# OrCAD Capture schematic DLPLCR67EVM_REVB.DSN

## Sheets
1 PAGE-07 Important Notice
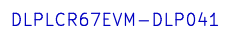
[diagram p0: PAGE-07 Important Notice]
2 PAGE-01 Title Page
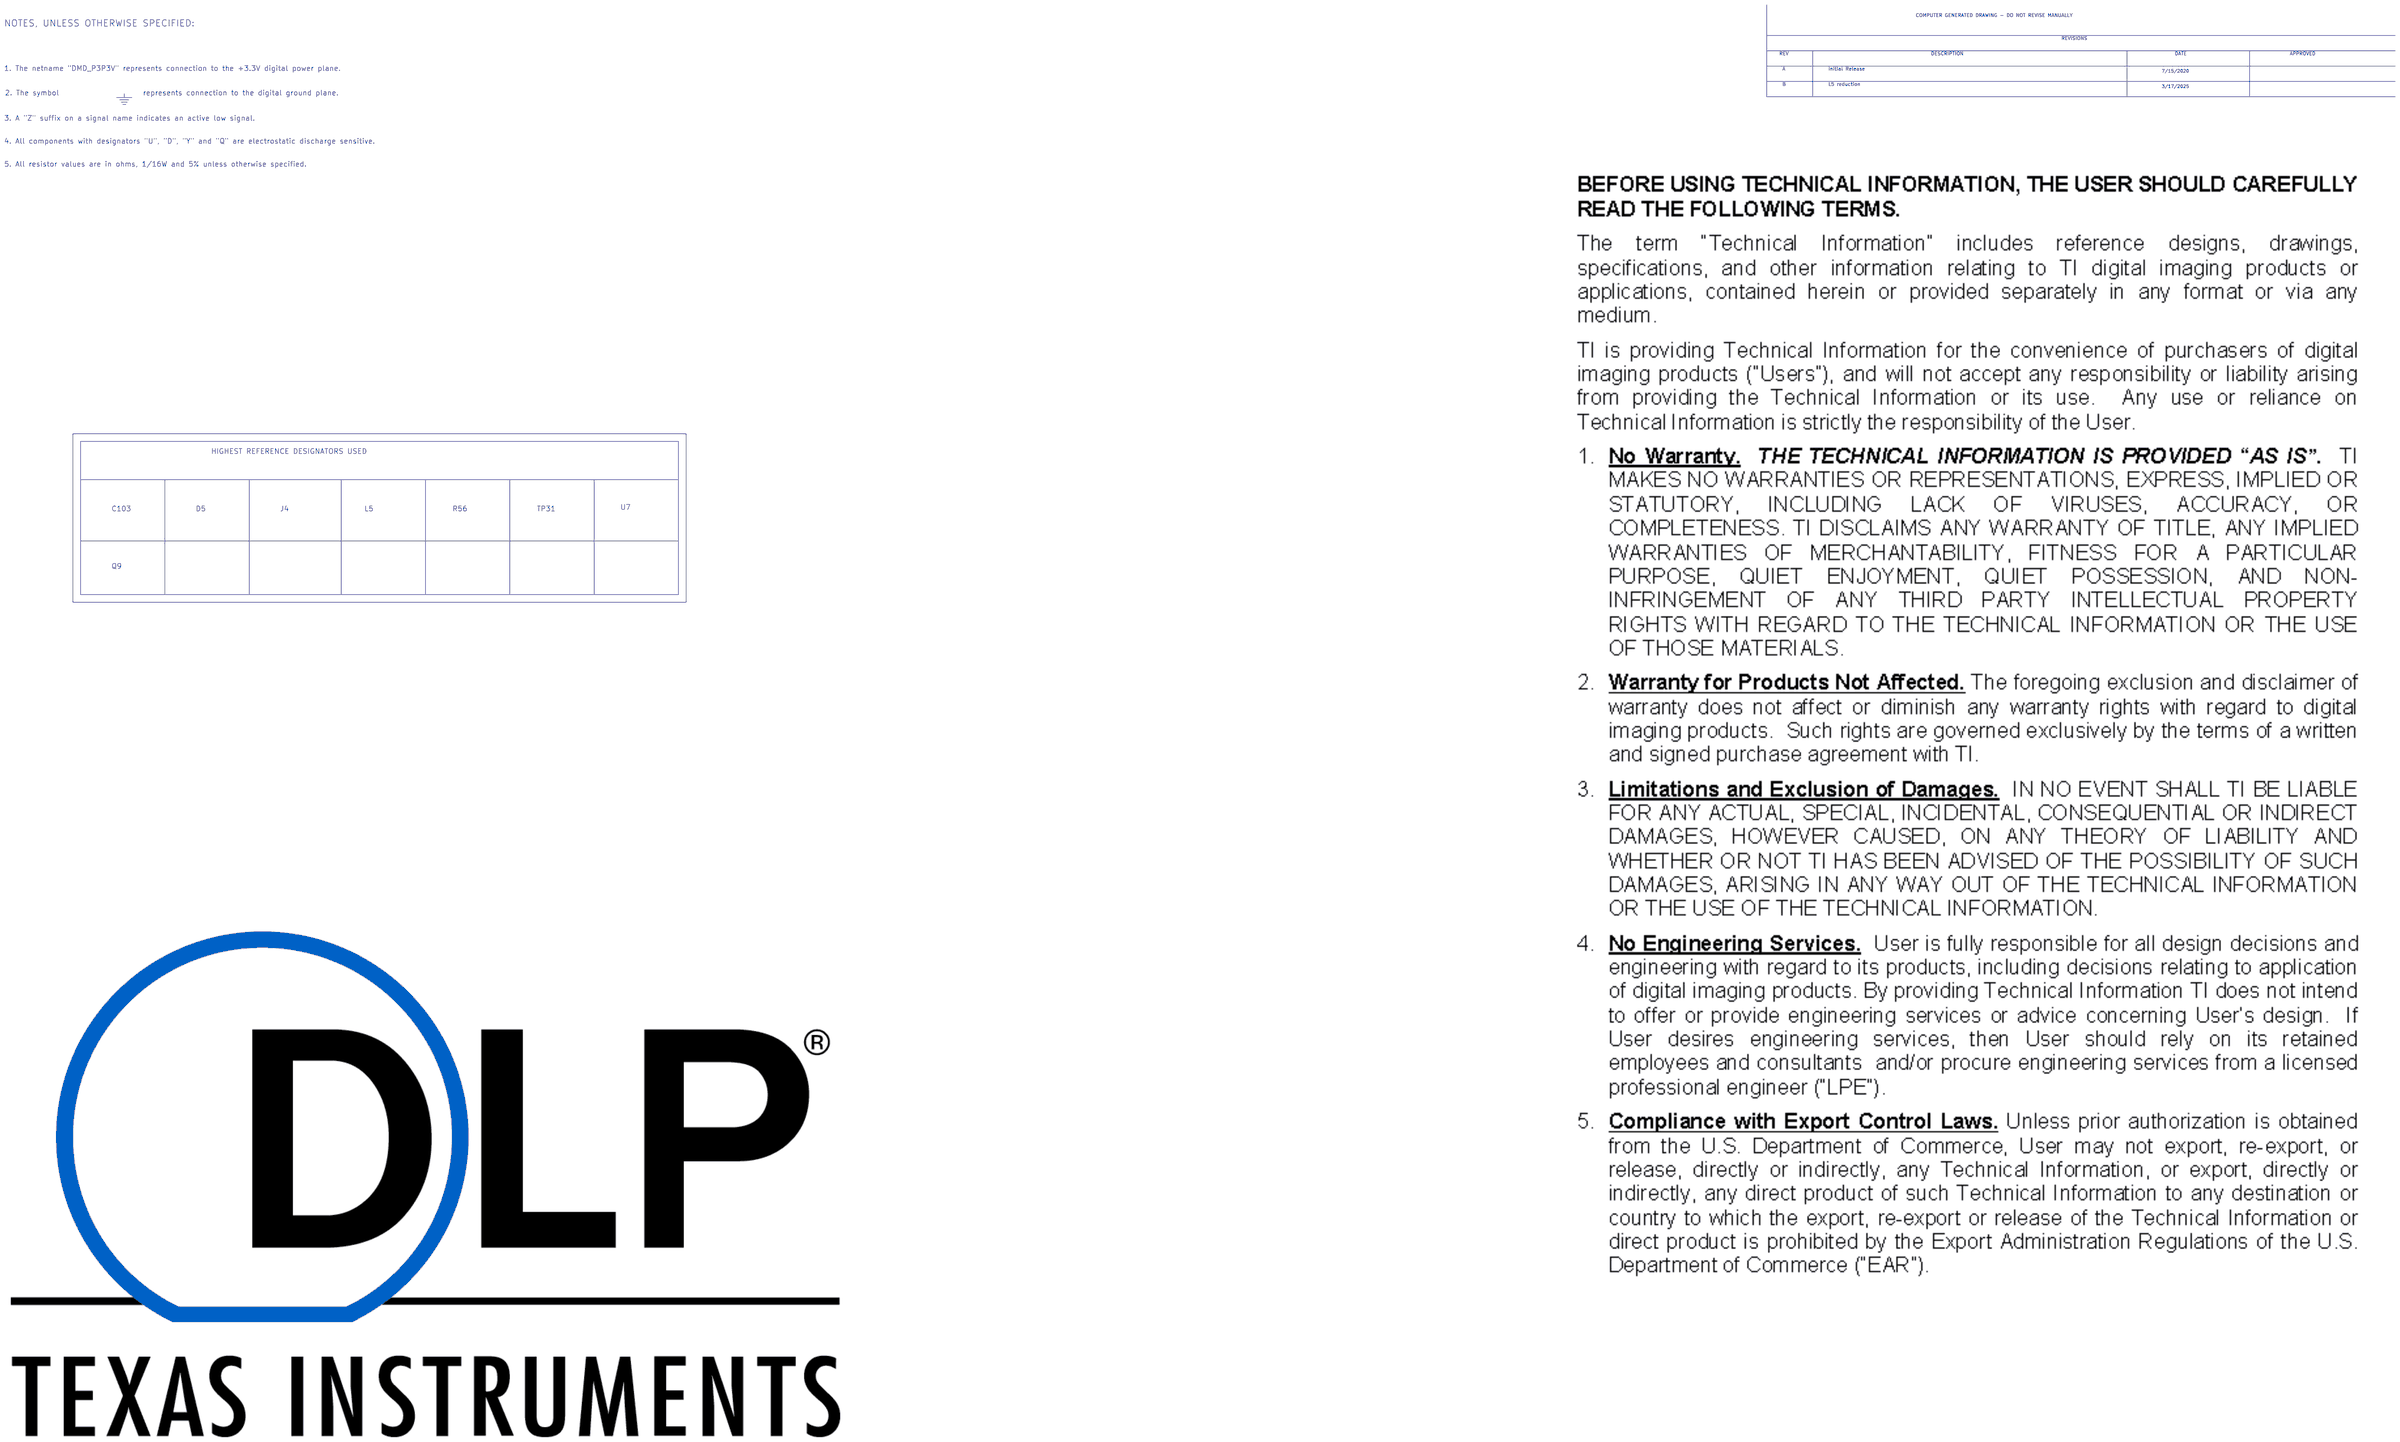
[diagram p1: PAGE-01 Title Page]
3 PAGE-02 Block Diagram
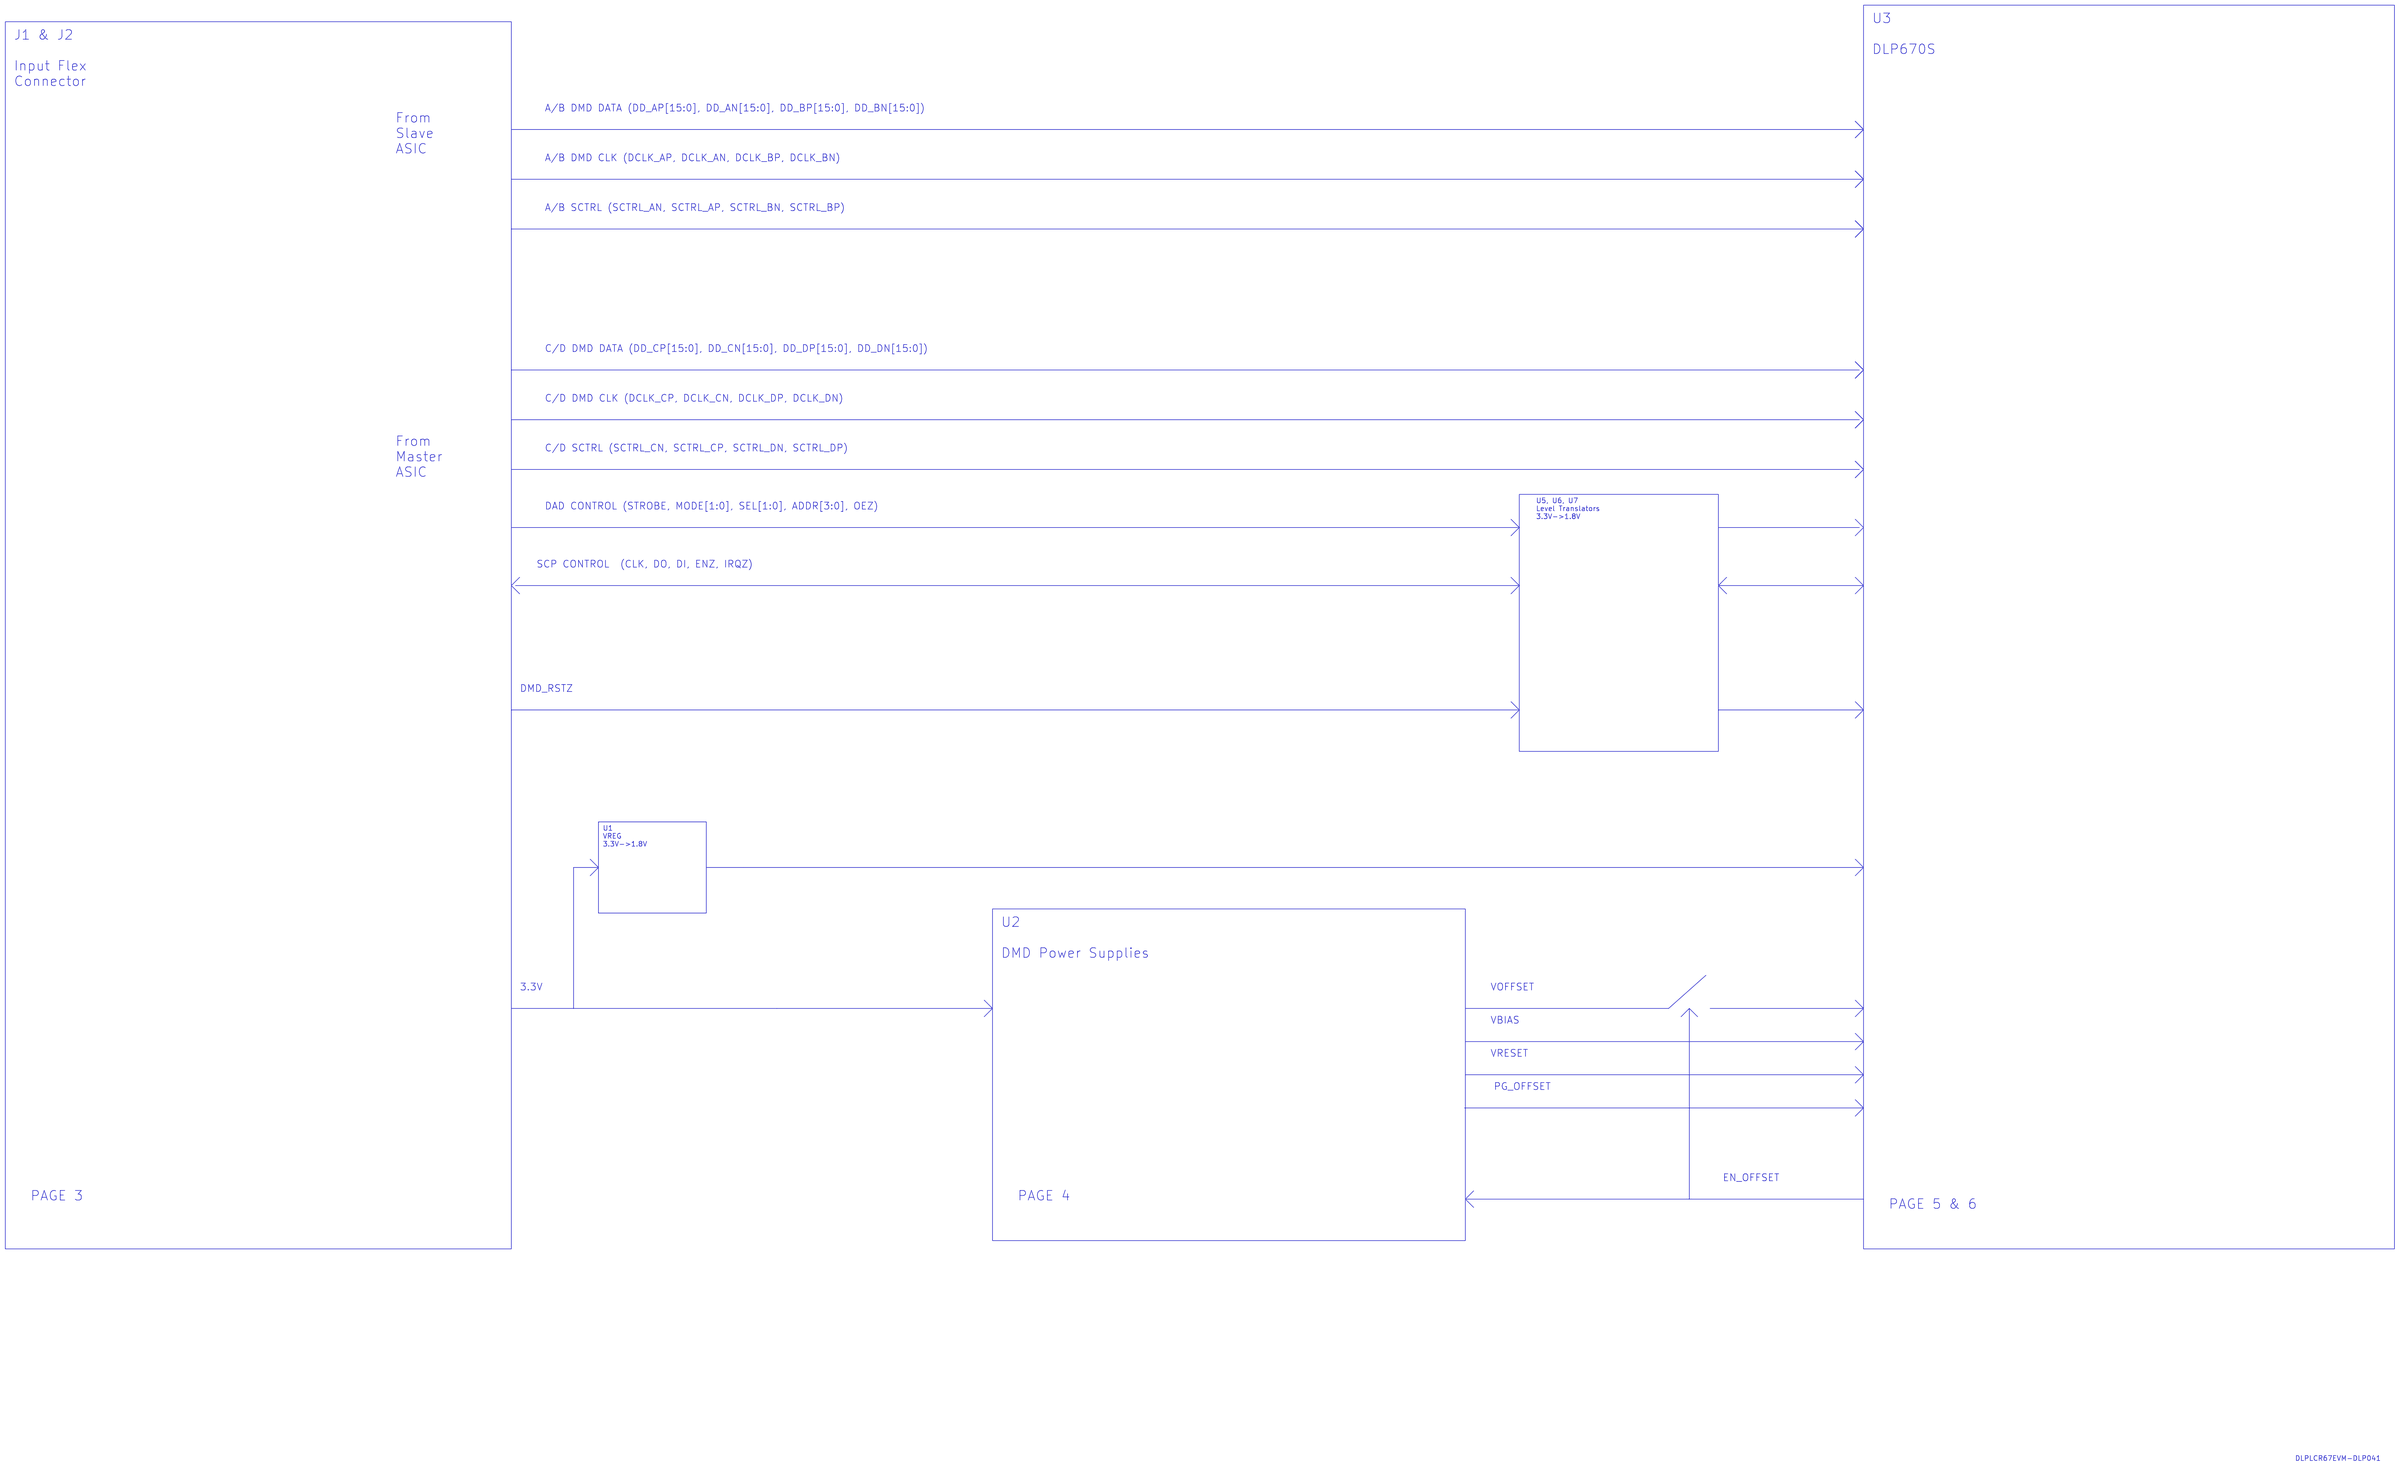
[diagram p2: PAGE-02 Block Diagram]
4 PAGE-03 Input Conn: size D
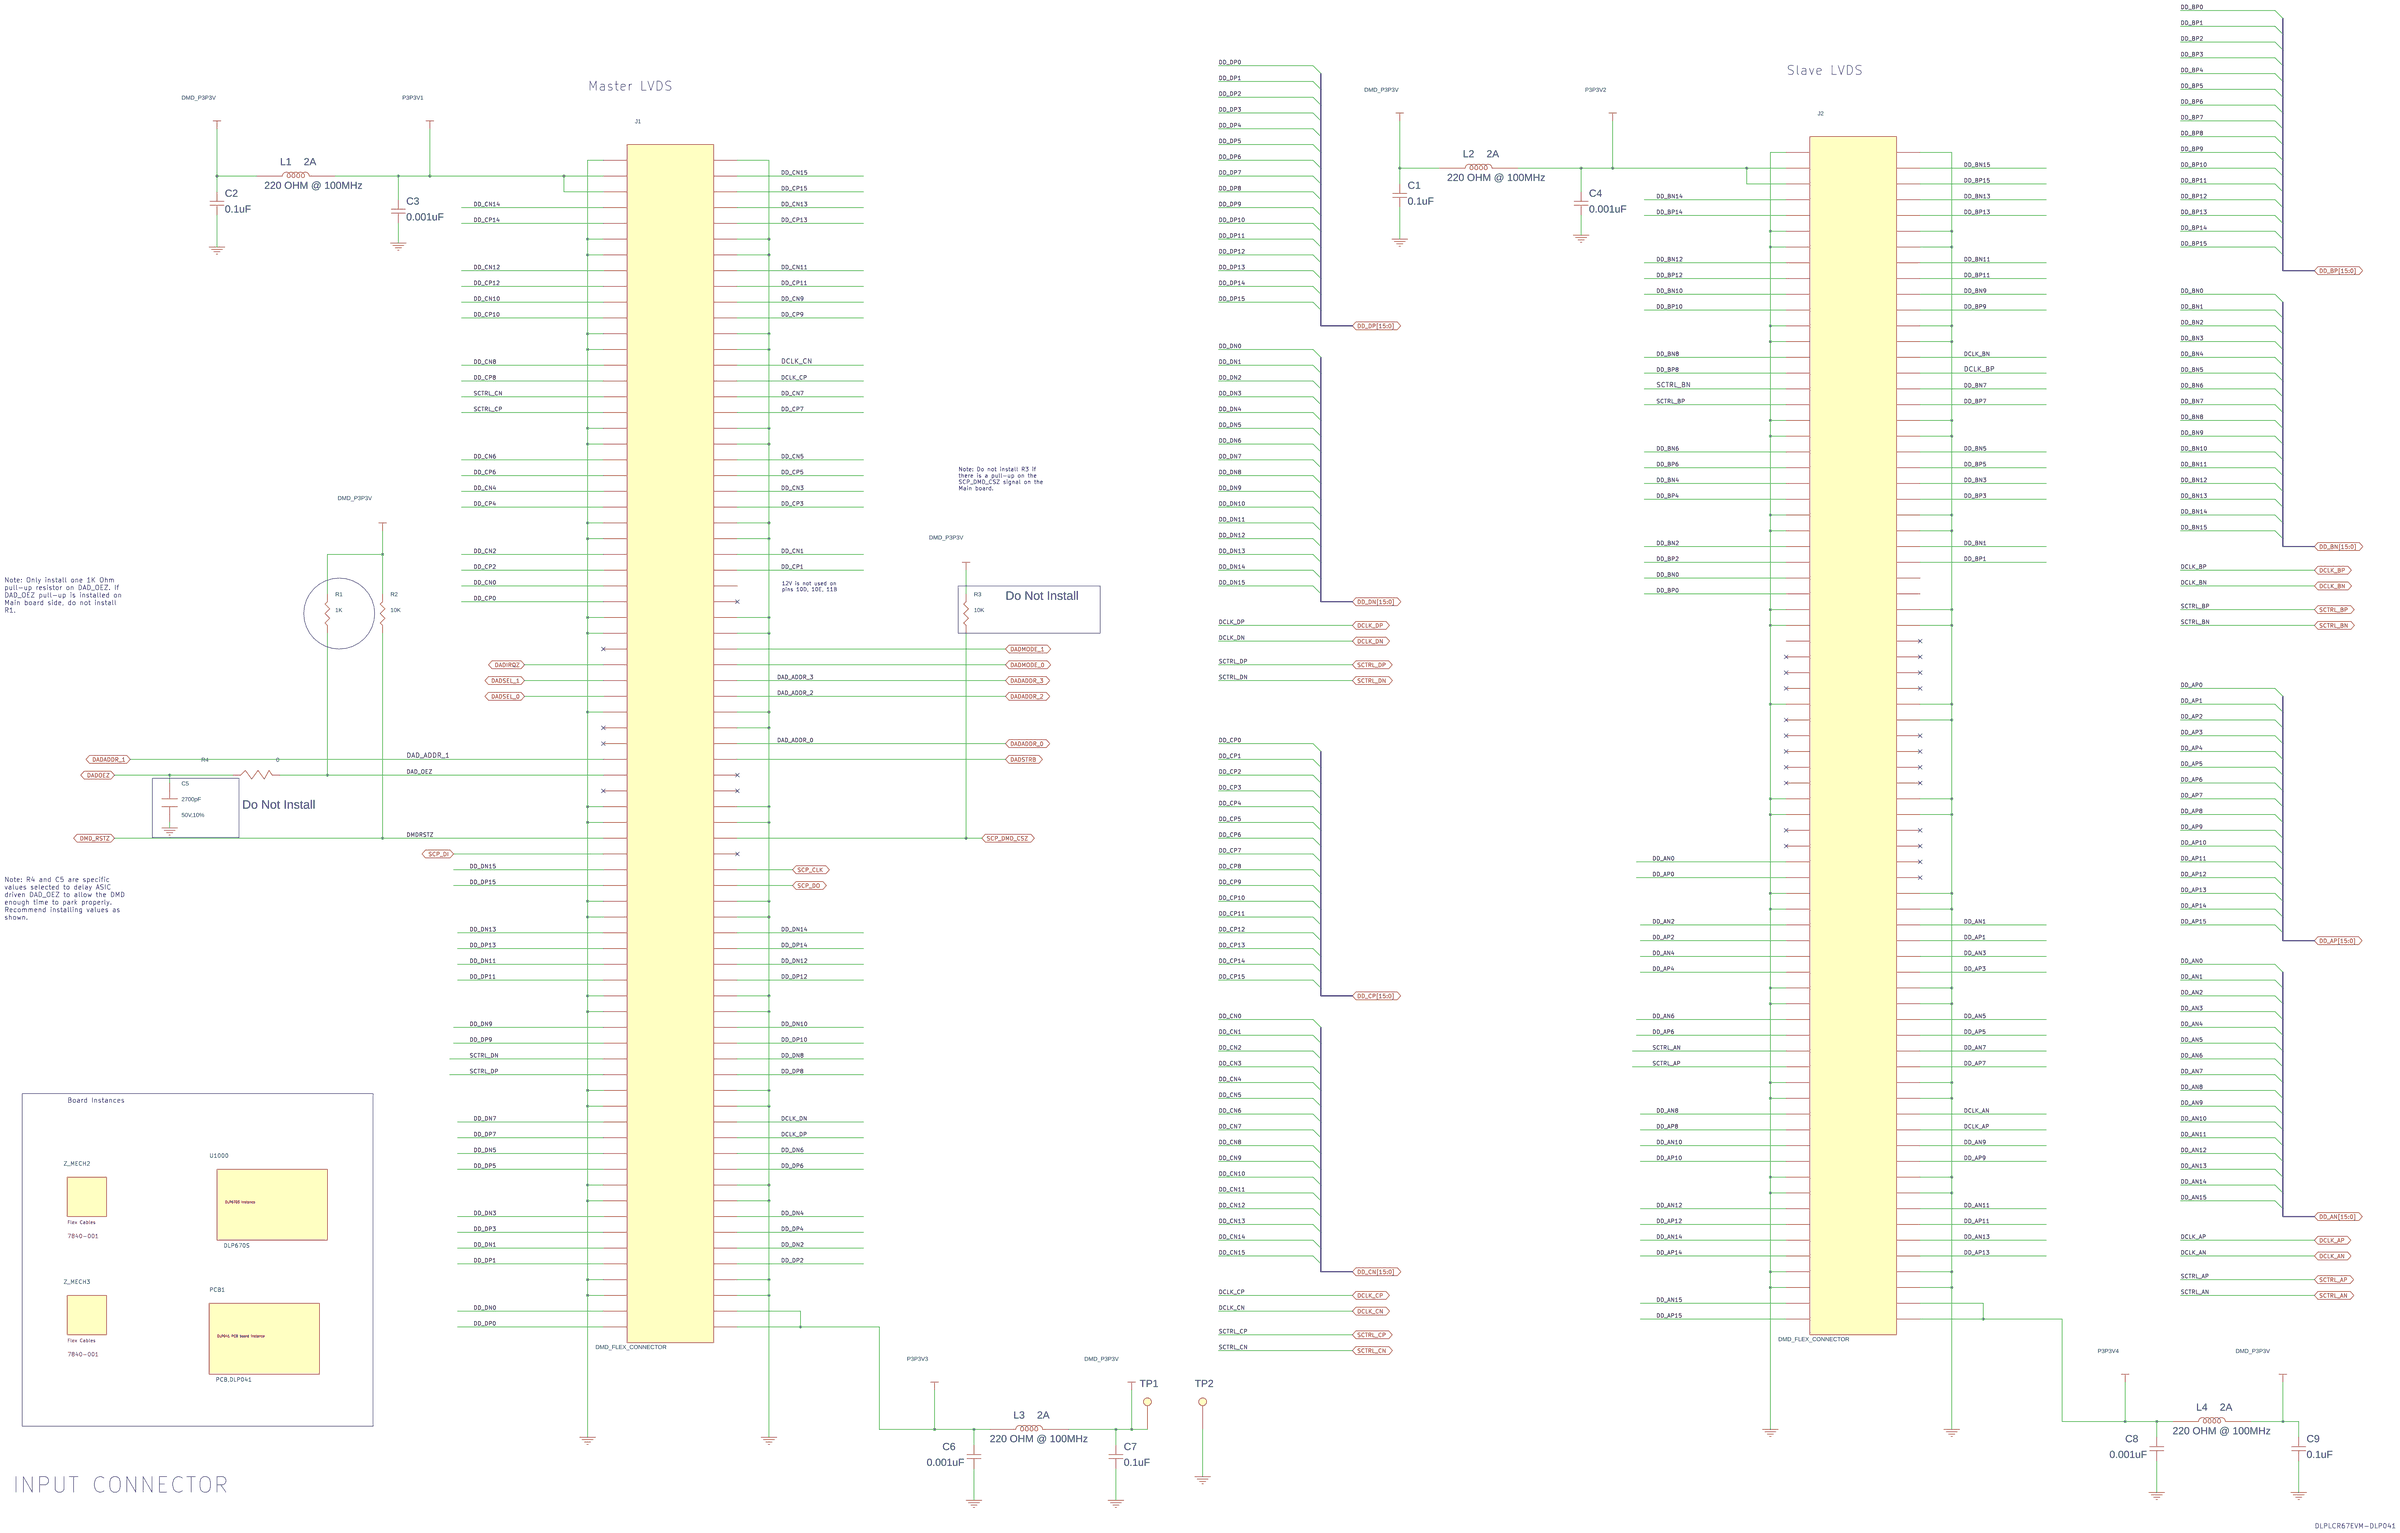
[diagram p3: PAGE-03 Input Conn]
5 PAGE-04 DMD Pwr Supplies: size D
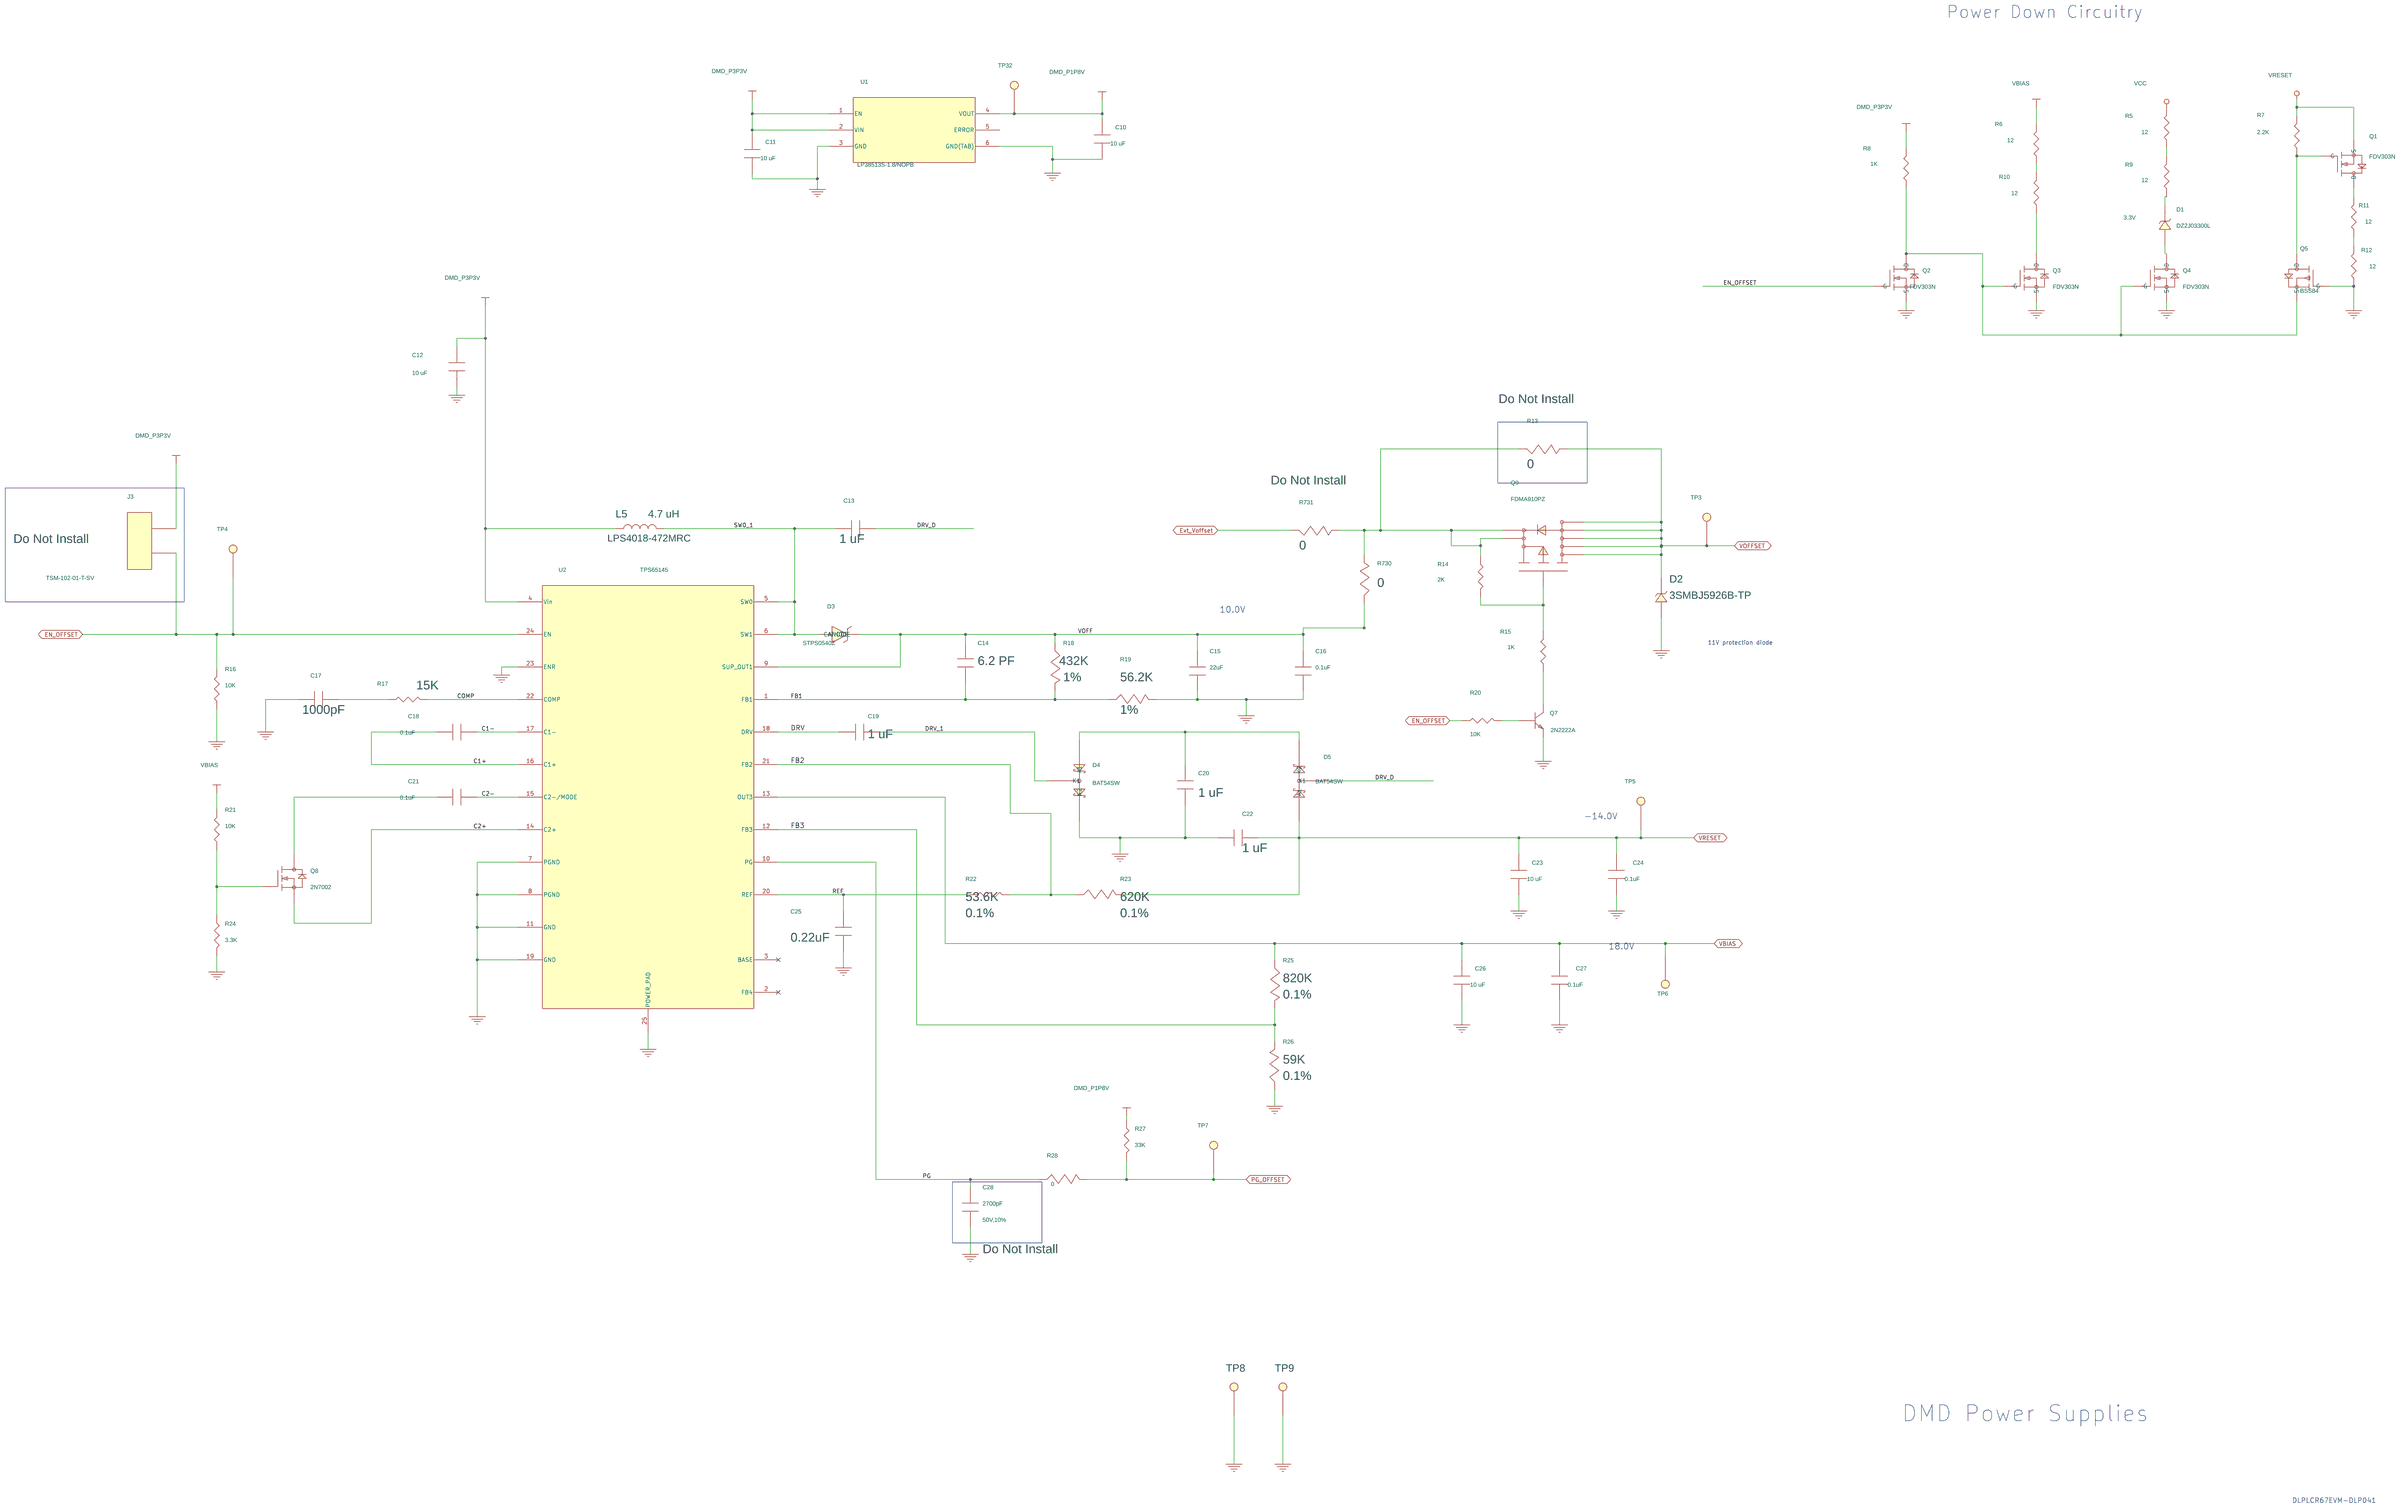
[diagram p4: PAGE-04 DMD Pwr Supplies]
6 PAGE-06 DMD Pwr/Gnd: size D
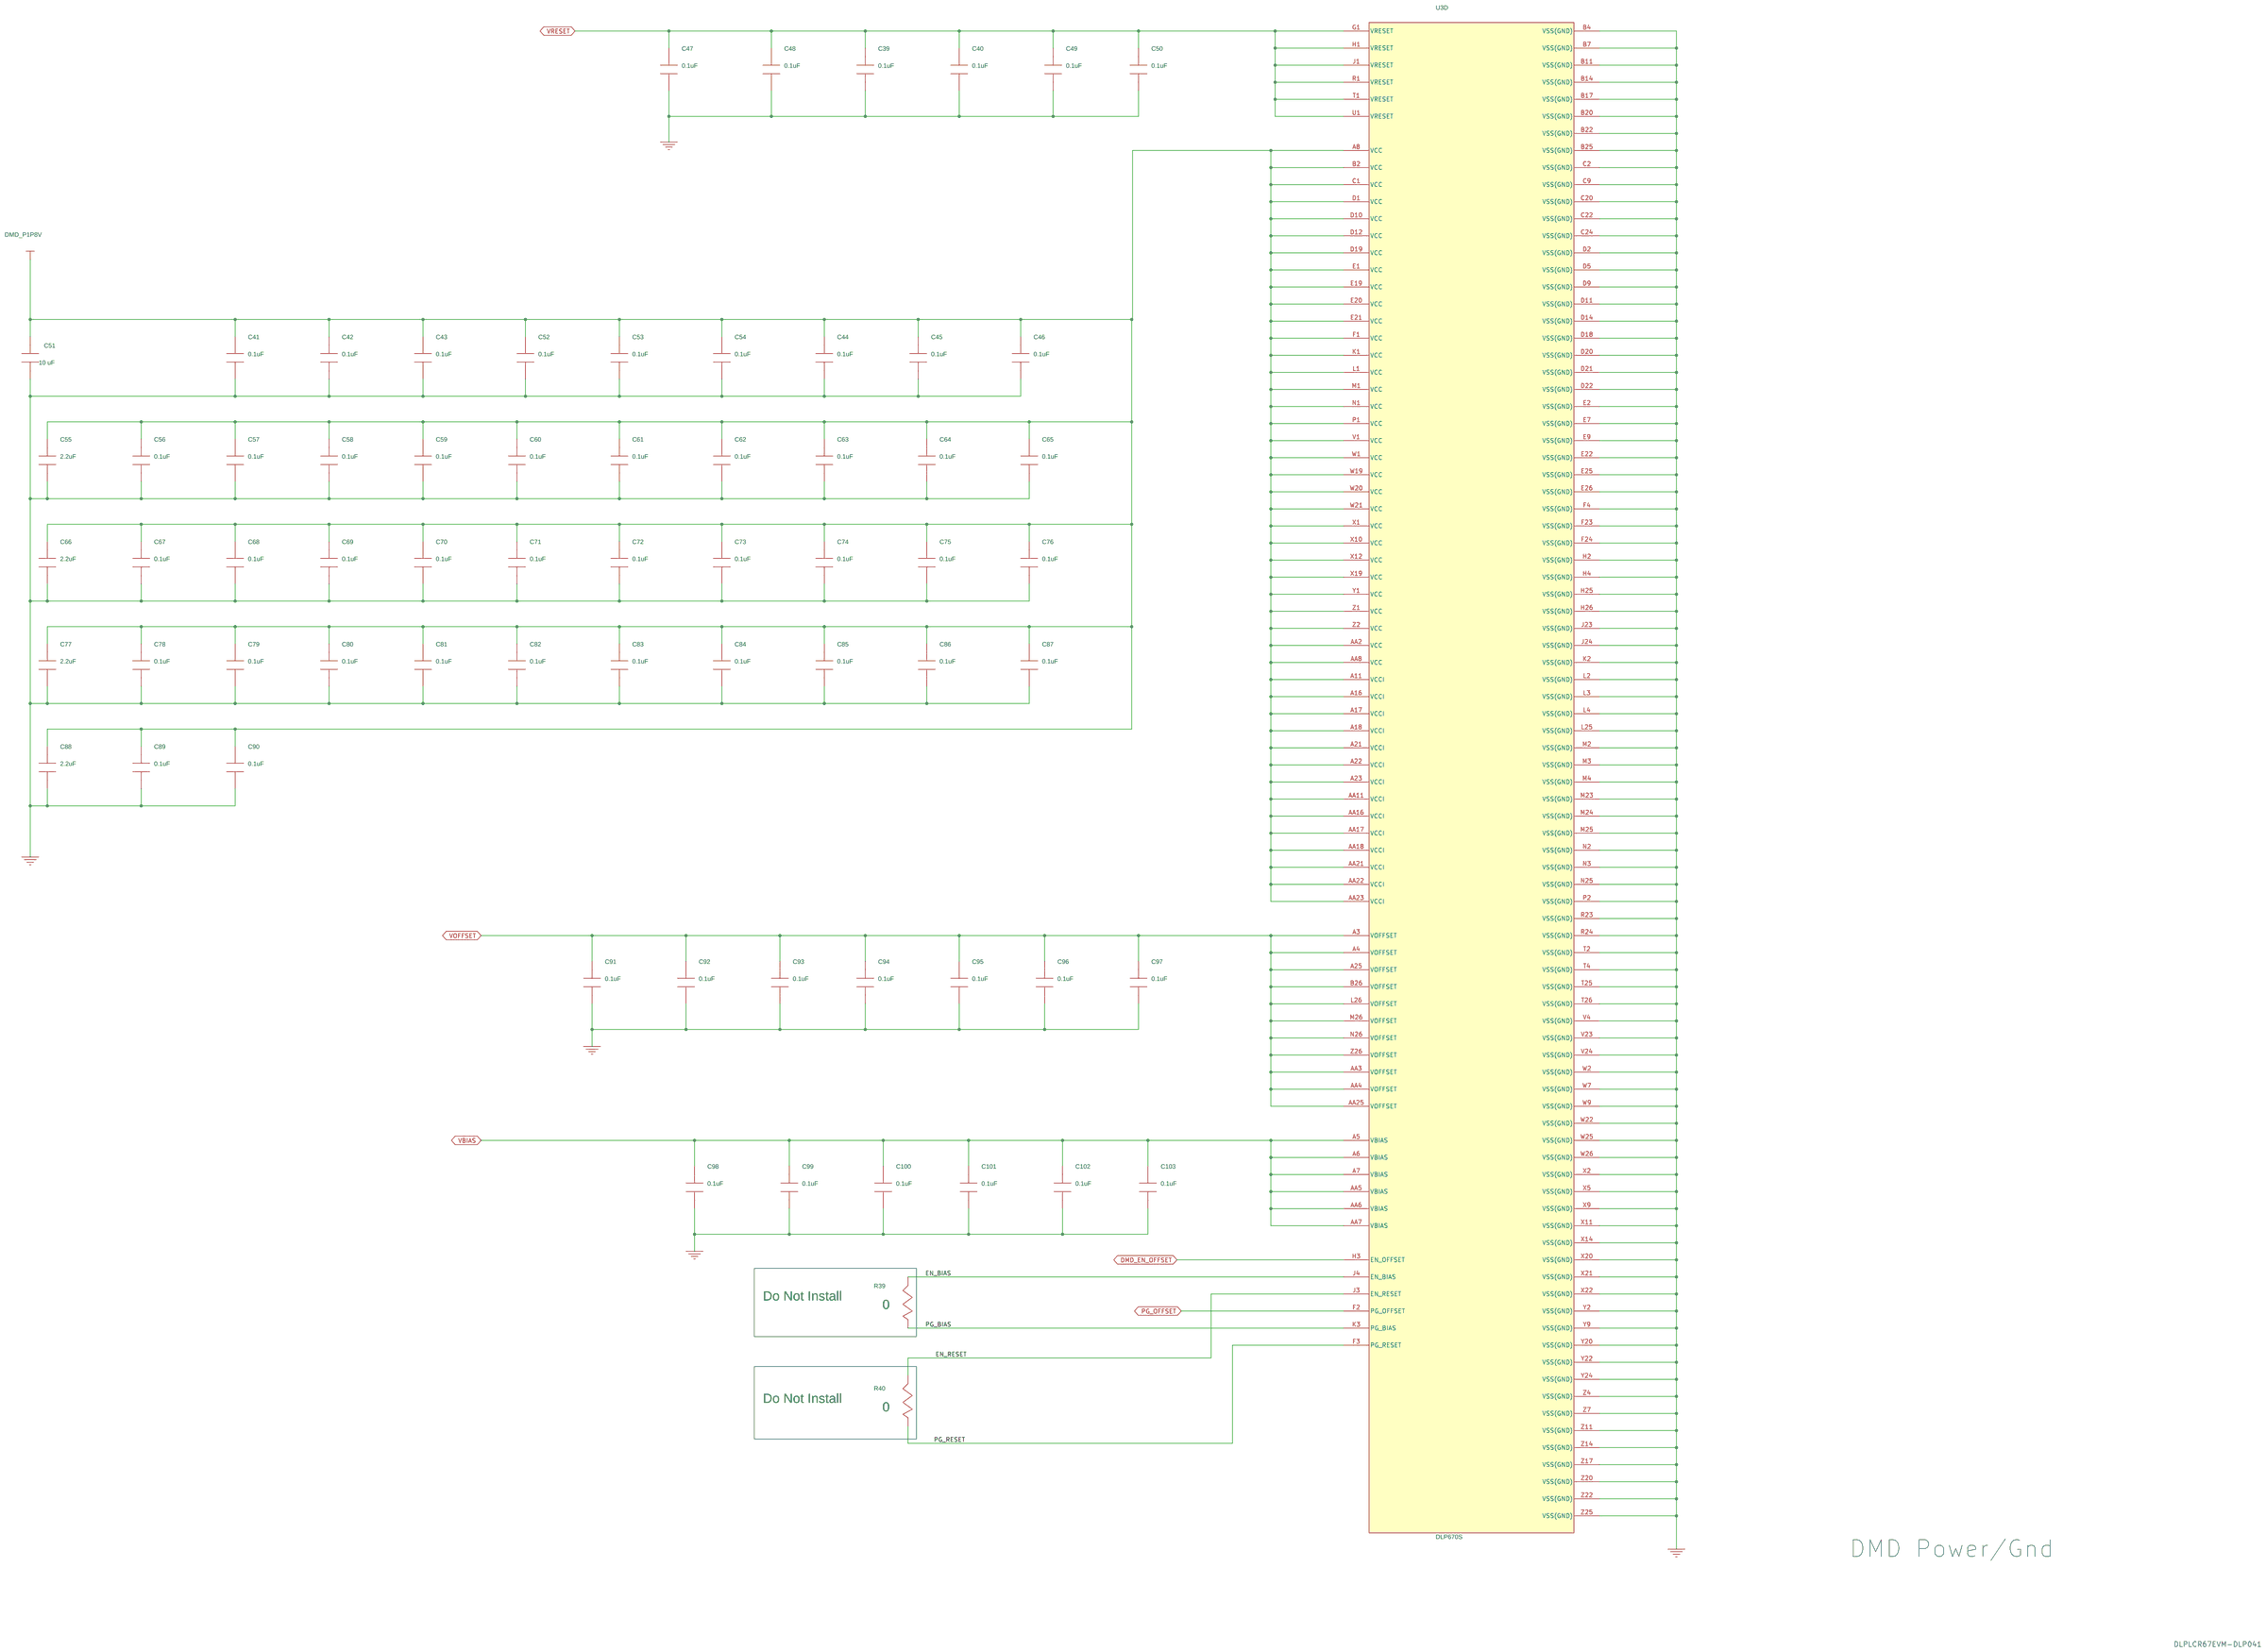
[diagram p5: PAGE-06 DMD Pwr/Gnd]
7 PAGE-05 DMD Data/Control: size D
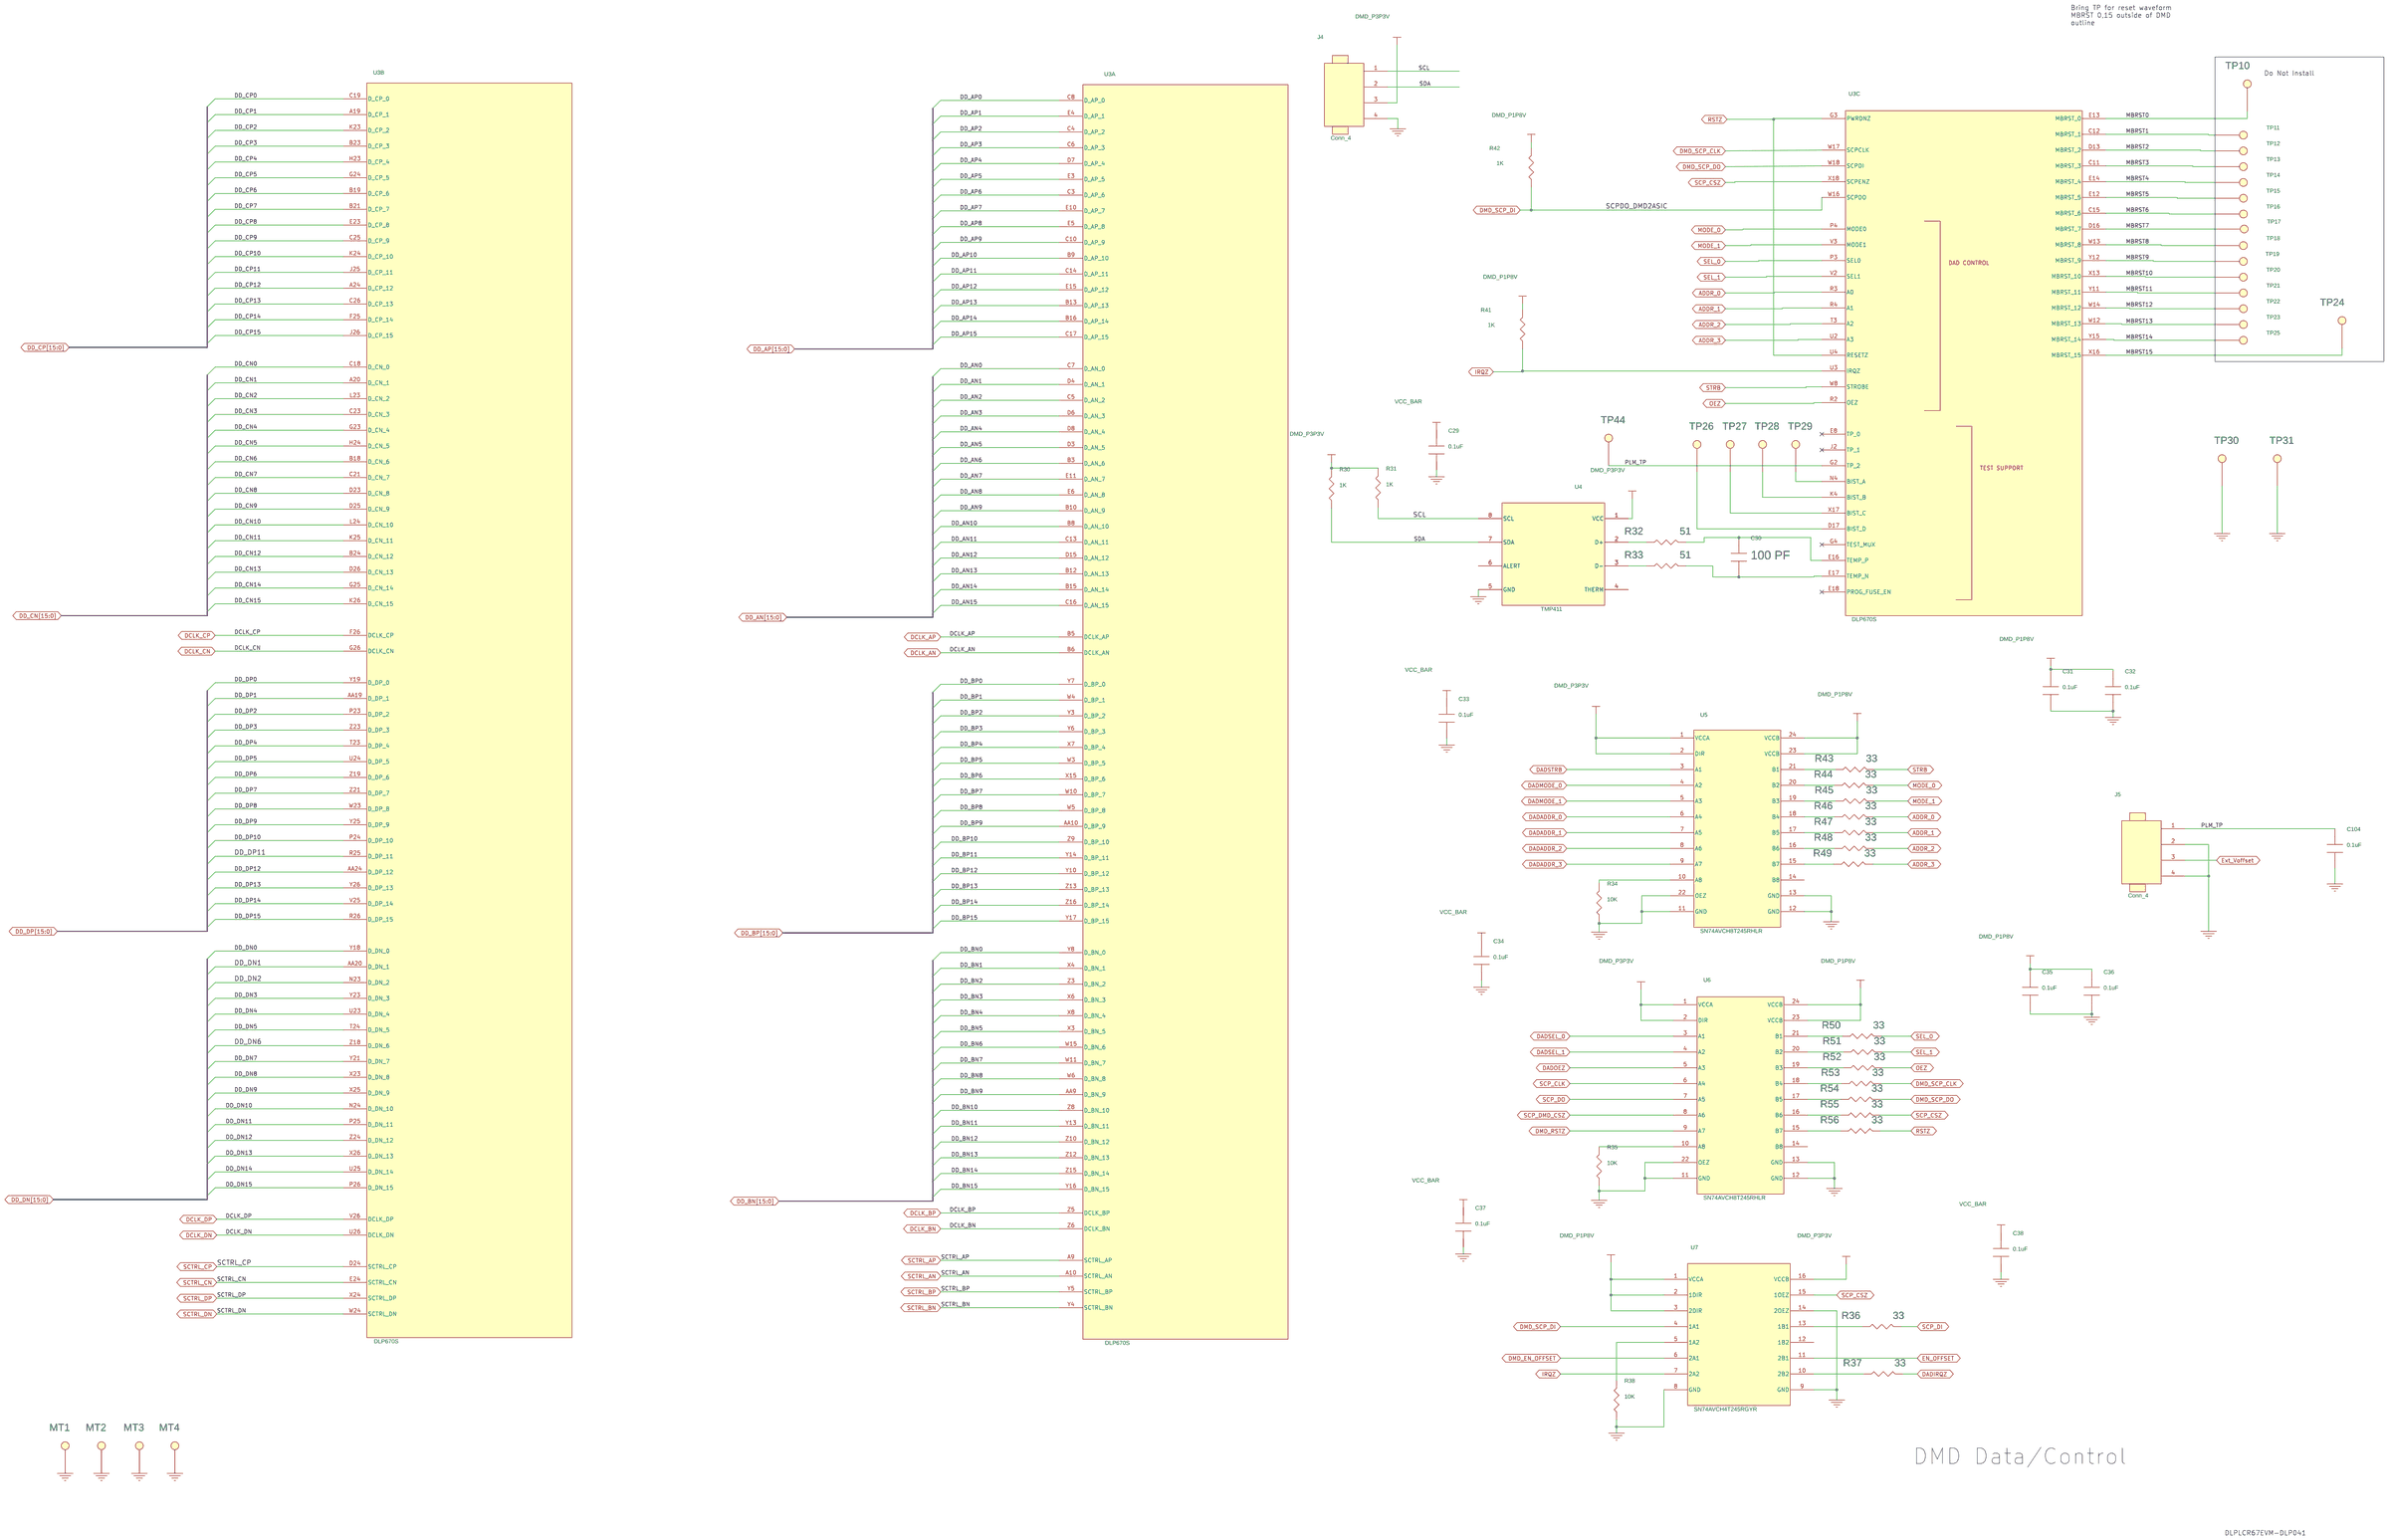
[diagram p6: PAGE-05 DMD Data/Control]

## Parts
sheet PAGE-03 Input Conn
C1  0.1uF  [0603AVX]
C2  0.1uF  [0603AVX]
C3  0.001uF  [0603AVX]
C4  0.001uF  [0603AVX]
C5  2700pF  [0402avx]
C6  0.001uF  [0603AVX]
C7  0.1uF  [0603AVX]
C8  0.001uF  [0603AVX]
C9  0.1uF  [0603AVX]
J1  DMD_FLEX_CONNECTOR  [CN150CUSTOM_REVB-MOD-NO-MH]
J2  DMD_FLEX_CONNECTOR  [CN150CUSTOM_REVB-MOD-NO-MH]
L1  220 OHM @ 100MHz  [0805avx]
L2  220 OHM @ 100MHz  [0805avx]
L3  220 OHM @ 100MHz  [0805avx]
L4  220 OHM @ 100MHz  [0805avx]
PCB1  PCB,DLP041
R1  1K  [0603AVX]
R2  10K  [0603AVX]
R3  10K  [0603AVX]
R4  0  [0603avx]
TP1  Testpoint  [TP40_24]
TP2  Testpoint  [TP40_24]
U1000  DLP670S
Z_MECH2  MECH
Z_MECH3  MECH
sheet PAGE-04 DMD Pwr Supplies
C10  10 uF  [1210]
C11  10 uF  [1210]
C12  10 uF  [1210]
C13  1 uF  [0603AVX]
C14  6.2 PF  [0402AVX]
C15  22uF  [1210]
C16  0.1uF  [0805avx]
C17  1000pF  [0805avx]
C18  0.1uF  [0805avx]
C19  1 uF  [0603AVX]
C20  1 uF  [0603AVX]
C21  0.1uF  [0805avx]
C22  1 uF  [0603AVX]
C23  10 uF  [1210]
C24  0.1uF  [0805avx]
C25  0.22uF  [0805AVX]
C26  10 uF  [1210]
C27  0.1uF  [0805avx]
C28  2700pF  [0402avx]
D1  3.3V  [SC-90A]
D2  11V  [DO214AA]
D3  STPS0540Z  [SOD123]
D4  BAT54SW  [sot323avx]
D5  BAT54SW  [sot323avx]
J3  TSM-102-01-T-SV  [CONN_2POS_2p54MM]
L5  4.7 uH  [IND_LPS4018]
Q1  N-CHANNEL MOSFET  [SOT23AVX]
Q2  N-CHANNEL MOSFET  [SOT23AVX]
Q3  N-CHANNEL MOSFET  [SOT23AVX]
Q4  N-CHANNEL MOSFET  [SOT23AVX]
Q5  BSS84  [SOT23AVX]
Q7  2N2222A  [SOT23AVXD]
Q8  2N7002  [SOT-23]
Q9  FDMA910PZ  [MicroFET_2x2]
R5  12  [0805]
R6  12  [0805]
R7  2.2K  [0402]
R8  1K  [0402]
R9  12  [0805]
R10  12  [0805]
R11  12  [0805]
R12  12  [0805]
R13  0  [0603avx]
R14  2K  [RES_0402]
R15  1K  [0402]
R16  10K  [0603AVX]
R17  15K  [0603AVX]
R18  432K  [0603avx]
R19  56.2K  [0603avx]
R20  10K  [0402]
R21  10K  [0603AVX]
R22  53.6K  [0603avx]
R23  620K  [0603avx]
R24  3.3K  [0402]
R25  820K  [RES0805]
R26  59K  [0603avx]
R27  33K  [0402]
R28  0  [0603avx]
R730  0  [0603avx]
R731  0  [0603avx]
TP3  Testpoint  [TP40_24_TH]
TP4  Testpoint  [TP40_24]
TP5  Testpoint  [TP40_24_TH]
TP6  Testpoint  [TP40_24_TH]
TP7  Testpoint  [TP40_24]
TP8  Testpoint  [TP40_24]
TP9  Testpoint  [TP40_24]
TP32  Testpoint  [TP40_24_TH]
U1  LP38513S-1.8/NOPB  [TO-263]
U2  TPS65145  [SOIC24-PWP_TI]
sheet PAGE-05 DMD Data/Control
C29  0.1uF  [0603avx]
C30  100 PF  [0402AVX]
C31  0.1uF  [0603avx]
C32  0.1uF  [0603avx]
C33  0.1uF  [0603avx]
C34  0.1uF  [0603avx]
C35  0.1uF  [0603avx]
C36  0.1uF  [0603avx]
C37  0.1uF  [0603avx]
C38  0.1uF  [0603avx]
C104  0.1uF  [0603avx]
J4  Conn_4  [CONN_4]
J5  Conn_4  [CONN_4]
MT1  MT2  [MT2]
MT2  MT2  [MT2]
MT3  MT2  [MT2]
MT4  MT2  [MT2]
R30  1K  [0603AVX]
R31  1K  [0603AVX]
R32  51  [0402AVX]
R33  51  [0402AVX]
R34  10K  [0603AVX]
R35  10K  [0603AVX]
R36  33  [0402AVX]
R37  33  [0402AVX]
R38  10K  [0603AVX]
R41  1K  [0402]
R42  1K  [0402]
R43  33  [0402AVX]
R44  33  [0402AVX]
R45  33  [0402AVX]
R46  33  [0402AVX]
R47  33  [0402AVX]
R48  33  [0402AVX]
R49  33  [0402AVX]
R50  33  [0402AVX]
R51  33  [0402AVX]
R52  33  [0402AVX]
R53  33  [0402AVX]
R54  33  [0402AVX]
R55  33  [0402AVX]
R56  33  [0402AVX]
TP10  Testpoint  [TP40_24_TH]
TP11  Testpoint  [TP40_24]
TP12  Testpoint  [TP40_24]
TP13  Testpoint  [TP40_24]
TP14  Testpoint  [TP40_24]
TP15  Testpoint  [TP40_24]
TP16  Testpoint  [TP40_24]
TP17  Testpoint  [TP40_24]
TP18  Testpoint  [TP40_24]
TP19  Testpoint  [TP40_24]
TP20  Testpoint  [TP40_24]
TP21  Testpoint  [TP40_24]
TP22  Testpoint  [TP40_24]
TP23  Testpoint  [TP40_24]
TP24  Testpoint  [TP40_24_TH]
TP25  Testpoint  [TP40_24_TH]
TP26  Testpoint  [TP40_24]
TP27  Testpoint  [TP40_24]
TP28  Testpoint  [TP40_24]
TP29  Testpoint  [TP40_24]
TP30  Testpoint  [TP40_24_TH]
TP31  Testpoint  [TP40_24]
TP44  Testpoint  [TP40_24]
U3  DLP670S  [DMD_S600_Socket]  (sections A,B,C,D)
U4  TMP411  [MSOP-8]
U5  SN74AVCH8T245RHLR  [QFN-24]
U6  SN74AVCH8T245RHLR  [QFN-24]
U7  SN74AVCH4T245RGYR  [VQFN]
sheet PAGE-06 DMD Pwr/Gnd
C39  0.1uF  [0603avx]
C40  0.1uF  [0603avx]
C41  0.1uF  [0603avx]
C42  0.1uF  [0603avx]
C43  0.1uF  [0603avx]
C44  0.1uF  [0603avx]
C45  0.1uF  [0603avx]
C46  0.1uF  [0603avx]
C47  0.1uF  [0603avx]
C48  0.1uF  [0603avx]
C49  0.1uF  [0603avx]
C50  0.1uF  [0603avx]
C51  10 uF  [1210]
C52  0.1uF  [0603avx]
C53  0.1uF  [0603avx]
C54  0.1uF  [0603avx]
C55  2.2uF  [0603avx]
C56  0.1uF  [0603avx]
C57  0.1uF  [0603avx]
C58  0.1uF  [0603avx]
C59  0.1uF  [0603avx]
C60  0.1uF  [0603avx]
C61  0.1uF  [0603avx]
C62  0.1uF  [0603avx]
C63  0.1uF  [0603avx]
C64  0.1uF  [0603avx]
C65  0.1uF  [0603avx]
C66  2.2uF  [0603avx]
C67  0.1uF  [0603avx]
C68  0.1uF  [0603avx]
C69  0.1uF  [0603avx]
C70  0.1uF  [0603avx]
C71  0.1uF  [0603avx]
C72  0.1uF  [0603avx]
C73  0.1uF  [0603avx]
C74  0.1uF  [0603avx]
C75  0.1uF  [0603avx]
C76  0.1uF  [0603avx]
C77  2.2uF  [0603avx]
C78  0.1uF  [0603avx]
C79  0.1uF  [0603avx]
C80  0.1uF  [0603avx]
C81  0.1uF  [0603avx]
C82  0.1uF  [0603avx]
C83  0.1uF  [0603avx]
C84  0.1uF  [0603avx]
C85  0.1uF  [0603avx]
C86  0.1uF  [0603avx]
C87  0.1uF  [0603avx]
C88  2.2uF  [0603avx]
C89  0.1uF  [0603avx]
C90  0.1uF  [0603avx]
C91  0.1uF  [0603avx]
C92  0.1uF  [0603avx]
C93  0.1uF  [0603avx]
C94  0.1uF  [0603avx]
C95  0.1uF  [0603avx]
C96  0.1uF  [0603avx]
C97  0.1uF  [0603avx]
C98  0.1uF  [0603avx]
C99  0.1uF  [0603avx]
C100  0.1uF  [0603avx]
C101  0.1uF  [0603avx]
C102  0.1uF  [0603avx]
C103  0.1uF  [0603avx]
R39  0  [0603avx]
R40  0  [0603avx]

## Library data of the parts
C1 C2 C7 C9 = CAP_NP: Capacitor; CCA ITEM: 1; MFG: AVX; Part Number: 0603YC104KAT2A; Rating: 16V; Tolerance: 10%; Type: X7R
C3 C4 C6 C8 = CAP_NP: Capacitor; CCA ITEM: 3; MFG: AVX; Part Number: 06035C102KAT2A; Rating: 50V; Tolerance: 10%; Type: X7R
C5 C28 = CAP_NP_dsize: Capacitor; Do Not Install: Do Not Install; ESR: <ESR>; ICA_MFR_NAME: PANASONIC; ICA_PARTNUM: $$2075017$$ECJ1VB1E104K; MFG: Yageo; Part Number: CC0402KRX7R9BB272; Rating: 50V; Rating/Tolerance: 50V,10%; Tolerance: 10%; Type: X7R
J1 J2 = cSTACK_FLEX_CONN_2: Connector; MFG: INTERCON SYSTEMS; Part Number: CN150CUSTOM_REVB
L1-L4 = FERRITE_L: Ferrite; CCA ITEM: 59; CURRENT: 2A; ICA_MFR_NAME: MURATA; ICA_PARTNUM: $$1507311$$BLM21PG221SG; MFG: MURATA; Part Number: BLM21PG221SN1D; Rating: 2A, 50mOhm; Tolerance: 25%
PCB1 = DLP026_0
R1 R30 R31 = R: Resistor; CCA ITEM: ?; Do Not Install: Do Not Install; MFG: Panasonic; Part Number: ERJ-3GEYJ102V; Rating: 1/10W; Tolerance: 5%
R2 R16 R21 R34 R35 R38 = R: Resistor; CCA ITEM: ?; MFG: Panasonic; Part Number: ERJ-3GEYJ103V; Rating: 1/10W; Tolerance: 5%
R3 = R: Resistor; CCA ITEM: ?; Do Not Install: Do Not Install; MFG: Panasonic; Part Number: ERJ-3GEYJ103V; Rating: 1/10W; Tolerance: 5%
R4 R28 = RESISTOR_dsize: Resistor; CCA ITEM: 110; ICA_MFR_NAME: PANASONIC; ICA_PARTNUM: $$1785380$$ERJ-3GSYJ330V; Mfg: Panasonic; Part Number: ERJ-3GEY0R00V; RATING/TOLERANCE: <RATING/TOLERANCE>; Rating: 1/10W
TP1 TP2 TP8 TP9 TP26-TP31 TP44 = Testpoint: Test point; Part Number: TMP-543
U1000 = DLP026_1: MFG: TI
Z_MECH2 Z_MECH3 = PCB: Flex Cables; MFG: Amphenol; Notes: Kitting item; Part Number: 7840-001
C10-C12 C23 C26 C51 = CAP_NP_dsize: Capacitor; ESR: <ESR>; Mfg: Murata; Part Number: GRM32DR61E106KA12L; Rating: 25V; Rating/Tolerance: 25V,10%; Tolerance: 10%; Type: X5R
C13 C19 C20 C22 = CAP_NP_dsize: Capacitor; Mfg: AVX; Part Number: 06033D105KAT2A; Rating: 25V; Tolerance: 10%; Type: X5R
C14 = CAP_NP_dsize: Capacitor; Mfg: Murata; Part Number: GJM1555C1H6R2CB01D; Rating: 50V; Type: NP0
C15 = CAP_NP_dsize: Capacitor; ESR: <ESR>; Mfg: Taiyo Yuden; Rating: 16V; Rating/Tolerance: 16V,20%; Tolerance: 20%; Type: X5R; part number: EMK325BJ226MM-T
C16 C24 C27 = CAP_NP_dsize: Capacitor; ESR: 0.1 OHM; ICA_MFR_NAME: NIC; ICA_PARTNUM: $$2075017$$NMC1206X7R104K50; Mfg: AVX; Part Number: 08055C104MAT2A; Rating: 50V; Rating/Tolerance: 50V, 20%; Tolerance: 20%; Type: X7R
C17 = CAP_NP_dsize: Capacitor; Mfg: Panasonic; Part Number: ECJ-2VB1H102K; Rating: 50V; Tolerance: 10%; Type: X7R
C18 C21 = CAP_NP_dsize: Capacitor; ESR: 0.1 OHM; ICA_MFR_NAME: NIC; ICA_PARTNUM: $$2075017$$NMC1206X7R104K50; Mfg: AVX; Part Number: 08055C104MAT2A; Rating: 50V; Rating/Tolerance: 50V; Tolerance: 20%; Type: X7R
C25 = CAP_NP_dsize: Capacitor; Mfg: TDK; Part Number: C2012X8R1E224K125AA; Rating: 25V; Tolerance: 10%; Type: X8R
D1 = DIODE_ZENER: Diode, Zener; Mfg: PANASONIC; Part Number: DZ2J03300L
D2 = DIODE_ZENER: DIODE Zener; CCA ITEM: 9; MFG: Microcommercial; Part Number: 3SMBJ5926B-TP; RATING: 3W; RATING/TOLERANCE: 5%; Tolerance: 5%
D3 = DIODE_SCHOTTKY_dsize: Diode Schottky; Mfg: STM; Rating: 40V 0.5A
D4 D5 = BAT54SW: Diode Schottky; ICA_MFR_NAME: PHILIPS SEMICONDUCTOR; ICA_PARTNUM: $$1491280$$BAT54SW; Mfg: NXP; Part Number: BAT54SW,115; Rating: 30V
J3 = CONN_HEADER_2POS_.100_SNGL_SMD: Connector; Do Not Install: Do Not Install; Mfg: Samtec
L5 = INDUCTOR: Inductor; CCA ITEM: 12; ICA_MFR_NAME: STEWARD; ICA_PARTNUM: $$731362$$MI0603J680R-10; MFG: COILCRAFT; Part Number: LPS4018-472MRC; RATING: 1.3 A, 0.125Ohm; TOLERANCE: 20%
Q1-Q4 = N-FET: MOSFET, N-Channel; MFG: FAIRCHILD SEMI; Part Number: FDV303N; RATING: 20V; TOLERANCE: 460MW
Q5 = N-FET_0: MOSFET, N-Channel; MFG: FAIRCHILD SEMI; RATING: 50V; TOLERANCE: 130MA
Q7 = 2N2222A: Transistor, NPN; MFG: FAIRCHILD; Part Number: MMBT2222A; RATING: 40V, 500mA; SOURCE: DIGI MMBT2222AFSCT-ND
Q8 = VN0610LL: MOSFET, N-Chan; Mfg: ON Semicondutor; Part Number: 2N7002L; Rating: 7.5 ohms @ 10 V, 500 mA
Q9 = FDMA910PZ: MOSFET, P-Chan; MFG: FAIRCHILD; Rating: 20 mOhm @ 9.4A, 4.5V
R5 R6 R9-R12 = R: Resistor; ALT_SYMBOLS: 0402-1MM; ICA_MFR_NAME: PANASONIC; ICA_PARTNUM: $$1785048$$ERJ-3GSYJ102; MFG: PANASONIC; Part Number: ERJ-6GEYJ120V; RATING: 1/8W; TOLERANCE: 5%
R7 = R: Resistor; ALT_SYMBOLS: 0402-1MM; ICA_MFR_NAME: PANASONIC; ICA_PARTNUM: $$1785048$$ERJ-3GSYJ102; MFG: PANASONIC; Part Number: ERJ-2GEJ222X; RATING: 1/10W; TOLERANCE: 5%
R8 R15 R41 R42 = R: Resistor; ALT_SYMBOLS: 0402-1MM; ICA_MFR_NAME: PANASONIC; ICA_PARTNUM: $$1785048$$ERJ-3GSYJ102; MFG: PANASONIC; Part Number: ERJ-2GEJ102X; RATING: 1/10W; TOLERANCE: 5%
R13 R39 R40 R731 = RESISTOR_dsize: Resistor; Do Not Install: Do Not Install; ICA_MFR_NAME: YAGEO; ICA_PARTNUM: $$482834$$RC0603JRF070R0; Mfg: Panasonic; Part Number: ERJ-3GEY0R00V; Rating: 1/10W
R14 = R: Resistor; ICA_MFR_NAME: PANASONIC; ICA_PARTNUM: $$1785048$$ERJ-3GSYJ102; MFG: PANASONIC; Part Number: ERJ-2GEJ202X; RATING: 1/10W; SOURCE: DIGI P2.0KJCT-ND; TOLERANCE: 5%
R17 = RES: Resistor; ICA_MFR_NAME: YAGEO; ICA_PARTNUM: $$2140285$$RC0603FR-0715KL; Mfg: Yageo; Part Number: RC0603FR-0715KL; Rating: 1/10W; Tolerance: 1%
R18 = RESISTOR_dsize: Resistor; Mfg: Panasonic; Part Number: ERJ-3EKF4323V; Rating: 1/10W; Tolerance: 1%
R19 = RESISTOR_dsize: Resistor; Mfg: Panasonic; Part Number: ERJ-3EKF5622V; Rating: 1/10W; Tolerance: 1%
R20 = RESISTOR: Resistor; Mfg: Panasonic; Part Number: ERJ-2GEJ103X; Rating: 1/10W; Tolerance: 5%
R22 = R: Resistor; ICA_MFR_NAME: PANASONIC; ICA_PARTNUM: $$1784362$$ERJ-3GEYJ753; Mfg: Panasonic; Part Number: ERA-3AEB5362V; Rating: 1/10W; Tolerance: 0.1%
R23 = RESISTOR_dsize: Resistor; Mfg: TE Connectivity; Part Number: CPF0603B620KE1; Rating: 1/16W; Tolerance: 0.1%
R24 = RESISTOR: Resistor; Mfg: Panasonic; Part Number: ERJ-2GEJ332X; Rating: 1/10W; tolerance: 5%
R25 = RESISTOR_dsize: Resistor; DigiKey Part Number: A103245CT-ND; Mfg: TE Connectivity; Part Number: CPF0805B820KE1; Rating: 1/10W; Tolerance: 0.1%
R26 = RESISTOR_dsize: Resistor; DigiKey Part Number: YAG4755CT-ND; Mfg: Yageo; Part Number: RT0603BRE0759KL; Rating: 1/10W; Tolerance: 0.1%
R27 = RESISTOR: Resistor; Mfg: Panasonic; Part Number: ERJ-2GEJ333X; Rating: 1/10W; Tolerance: 5%
R730 = RESISTOR_dsize: Resistor; ICA_MFR_NAME: YAGEO; ICA_PARTNUM: $$482834$$RC0603JRF070R0; Mfg: Panasonic; Part Number: ERJ-3GEY0R00V; Rating: 1/10W
TP3-TP7 TP32 = Testpoint: Test Point; Part Number: TMP-543
U1 = LP38513S-1.8_NOPB: IC, Voltage Regulator; MFG: TI
U2 = TPS65145_11: IC Voltage Regulator; Mfg: TI; Part Number: TPS65145PWP
C29 C31-C50 C52-C54 C56-C65 C67-C70 C72-C74 C76 C78-C80 C82-C87 C89-C104 = CAP_NP_dsize: Capacitor; ESR: <ESR>; ICA_MFR_NAME: PANASONIC; ICA_PARTNUM: $$2075017$$ECJ1VB1E104K; Mfg: TDK; Part Number: C1608X7R1E104K080AA; Rating: 25V; Rating/Tolerance: 25V,10%; Tolerance: 10%; Type: X7R
C30 = CAP_NP_dsize: Capacitor; Mfg: AVX; Part Number: 04025C101KAT2A; Rating: 50V; Type: X7R
J4 J5 = Conn_4: Connector, 4 Pin; MFG: Molex; Part Number: 0532610471
MT1-MT4 = Testpoint: Test point; DNI: DNI
R32 R33 = R: Resistor; CCA ITEM: 13; MFG: Panasonic; Part Number: ERJ-2GEJ510X; Rating: 1/10W; Tolerance: 5%
R36 R37 R43-R56 = R: Resistor; CCA ITEM: 13; MFG: Yageo; Part Number: RC0402FR-0733RP; Rating: 1/16W; Tolerance: 1%
TP10 TP24 = Testpoint: Test point; DNI: DNI; Part Number: TMP-543
TP11-TP23 TP25 = Testpoint: Test Point; DNI: DNI; Part Number: TMP-543
U3 = DMD_0P7_TRP_S610: IC, DMD; MFG: TI DLP; Part Number: PZ35021-2641-01H
U4 = TMP411: IC, Temp Sensor; MFG: TI; Part Number: TMP411ADGKR
U5 U6 = SN74AVCH8T245RHLR: IC, Level Translator; MFG: TI
U7 = SN74AVCH4T245RGYR: IC, Level Translator; MFG: TI
C55 C66 C77 C88 = CAP_NP_dsize: Capacitor; ESR: <ESR>; ICA_MFR_NAME: PANASONIC; ICA_PARTNUM: $$2075017$$ECJ1VB1E104K; Mfg: Murata; Part Number: GRM188R61A225ME34D; Rating: 10V; Rating/Tolerance: 10V,10%; Tolerance: 20%; Type: X5R
C71 = CAP_NP_dsize: Capacitor; ESR: <ESR>; ICA_MFR_NAME: PANASONIC; ICA_PARTNUM: $$2075017$$ECJ1VB1E104K; Mfg: TDK; Part Number: C1608X7R1EC1608X7R1E104K080AA104K; Rating: 25V; Rating/Tolerance: 25V,10%; Tolerance: 10%; Type: X7R
C75 = CAP_NP_dsize: Capacitor; ESR: <ESR>; ICA_MFR_NAME: PANASONIC; ICA_PARTNUM: $$2075017$$ECJ1VB1E104K; Mfg: TDK; Part Number: C1608X7R1E104K080AA / 4K; Rating: 25V; Rating/Tolerance: 25V,10%; Tolerance: 10%; Type: X7R
C81 = CAP_NP_dsize: Capacitor; ESR: <ESR>; ICA_MFR_NAME: PANASONIC; ICA_PARTNUM: $$2075017$$ECJ1VB1E104K; Mfg: TDK; Part Number: C1608X7R1E104K080AA / K; Rating: 25V; Rating/Tolerance: 25V,10%; Tolerance: 10%; Type: X7R

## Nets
GND: C1.2 C2.2 C3.2 C4.2 C5.2 C6.2 C7.2 C8.2 C9.2 C10.1 C11.1 C12.1 C15.2 C16.2 C17.1 C20.2 C22.2 C23.1 C24.2 C25.2 C26.1 C27.2 C28.2 C29.2 C31.2 C32.2 C33.2 C34.2 C35.2 C36.2 C37.2 C38.2 C39.2 C40.2 C41.2 C42.2 C43.2 C44.2 C45.2 C46.2 C47.2 C48.2 C49.2 C50.2 C51.1 C52.2 C53.2 C54.2 C55.2 C56.2 C57.2 C58.2 C59.2 C60.2 C61.2 C62.2 C63.2 C64.2 C65.2 C66.2 C67.2 C68.2 C69.2 C70.2 C71.2 C72.2 C73.2 C74.2 C75.2 C76.2 C77.2 C78.2 C79.2 C80.2 C81.2 C82.2 C83.2 C84.2 C85.2 C86.2 C87.2 C88.2 C89.2 C90.2 C91.2 C92.2 C93.2 C94.2 C95.2 C96.2 C97.2 C98.2 C99.2 C100.2 C101.2 C102.2 C103.2 C104.2 D2.2(ANODE) D4.2(K2) J1.1A J1.1D J1.2C J1.2F J1.3A J1.3D J1.4C J1.4F J1.5A J1.5D J1.6C J1.6F J1.7A J1.7D J1.8C J1.8F J1.9A J1.9D J1.10C J1.10F J1.11A J1.11D J1.12C J1.12F J1.13D J1.14C J1.14F J1.15A J1.15D J1.16C J1.16F J1.17A J1.17D J1.18C J1.18F J1.19A J1.19D J1.20C J1.20F J1.21A J1.21D J1.22C J1.22F J1.23A J1.23D J1.24C J1.24F J1.25A J1.25D J2.1A J2.1D J2.2C J2.2F J2.3A J2.3D J2.4C J2.4F J2.5A J2.5D J2.6C J2.6F J2.7A J2.7D J2.8C J2.8F J2.9A J2.9D J2.10C J2.10F J2.11A J2.11D J2.12C J2.12F J2.13D J2.14C J2.14F J2.15A J2.15D J2.16C J2.16F J2.17A J2.17D J2.18C J2.18F J2.19A J2.19D J2.20C J2.20F J2.21A J2.21D J2.22C J2.22F J2.23A J2.23D J2.24C J2.24F J2.25A J2.25D J4.4 J5.2 J5.4 MT1.1 MT2.1 MT3.1 MT4.1 Q2.2(S) Q3.2(S) Q4.2(S) Q5.1(G) Q7.1(EMITTER) R12.2 R16.1 R19.2 R24.2 R26.1 R34.1 R35.1 R38.1 TP2.1 TP8.1 TP9.1 TP30.1 TP31.1 U1.3(GND) U1.6(GND(TAB)) U2.7(PGND) U2.8(PGND) U2.11(GND) U2.19(GND) U2.23(ENR) U2.25(POWER_PAD) U3.B4(VSS(GND)) U3.B7(VSS(GND)) U3.B11(VSS(GND)) U3.B14(VSS(GND)) U3.B17(VSS(GND)) U3.B20(VSS(GND)) U3.B22(VSS(GND)) U3.B25(VSS(GND)) U3.C2(VSS(GND)) U3.C9(VSS(GND)) U3.C20(VSS(GND)) U3.C22(VSS(GND)) U3.C24(VSS(GND)) U3.D2(VSS(GND)) U3.D5(VSS(GND)) U3.D9(VSS(GND)) U3.D11(VSS(GND)) U3.D14(VSS(GND)) U3.D18(VSS(GND)) U3.D20(VSS(GND)) U3.D21(VSS(GND)) U3.D22(VSS(GND)) U3.E2(VSS(GND)) U3.E7(VSS(GND)) U3.E9(VSS(GND)) U3.E22(VSS(GND)) U3.E25(VSS(GND)) U3.E26(VSS(GND)) U3.F4(VSS(GND)) U3.F23(VSS(GND)) U3.F24(VSS(GND)) U3.H2(VSS(GND)) U3.H4(VSS(GND)) U3.H25(VSS(GND)) U3.H26(VSS(GND)) U3.J23(VSS(GND)) U3.J24(VSS(GND)) U3.K2(VSS(GND)) U3.L2(VSS(GND)) U3.L3(VSS(GND)) U3.L4(VSS(GND)) U3.L25(VSS(GND)) U3.M2(VSS(GND)) U3.M3(VSS(GND)) U3.M4(VSS(GND)) U3.M23(VSS(GND)) U3.M24(VSS(GND)) U3.M25(VSS(GND)) U3.N2(VSS(GND)) U3.N3(VSS(GND)) U3.N25(VSS(GND)) U3.P2(VSS(GND)) U3.R23(VSS(GND)) U3.R24(VSS(GND)) U3.T2(VSS(GND)) U3.T4(VSS(GND)) U3.T25(VSS(GND)) U3.T26(VSS(GND)) U3.V4(VSS(GND)) U3.V23(VSS(GND)) U3.V24(VSS(GND)) U3.W2(VSS(GND)) U3.W7(VSS(GND)) U3.W9(VSS(GND)) U3.W22(VSS(GND)) U3.W25(VSS(GND)) U3.W26(VSS(GND)) U3.X2(VSS(GND)) U3.X5(VSS(GND)) U3.X9(VSS(GND)) U3.X11(VSS(GND)) U3.X14(VSS(GND)) U3.X20(VSS(GND)) U3.X21(VSS(GND)) U3.X22(VSS(GND)) U3.Y2(VSS(GND)) U3.Y9(VSS(GND)) U3.Y20(VSS(GND)) U3.Y22(VSS(GND)) U3.Y24(VSS(GND)) U3.Z4(VSS(GND)) U3.Z7(VSS(GND)) U3.Z11(VSS(GND)) U3.Z14(VSS(GND)) U3.Z17(VSS(GND)) U3.Z20(VSS(GND)) U3.Z22(VSS(GND)) U3.Z25(VSS(GND)) U4.5(GND) U5.11(GND) U5.12(GND) U5.13(GND) U5.22(OEZ) U6.11(GND) U6.12(GND) U6.13(GND) U6.22(OEZ) U7.8(GND) U7.9(GND) U7.14(2OEZ)
ADDR_0: R46.2 U3.R3(A0)
ADDR_1: R47.2 U3.R4(A1)
ADDR_2: R48.2 U3.T3(A2)
ADDR_3: R49.2 U3.U2(A3)
C1+: C18.1 U2.16(C1+)
C1-: C18.2 U2.17(C1-)
C2+: Q8.1(SOURCE) U2.14(C2+)
C2-: C21.2 U2.15(C2-/MODE)
COMP: R17.2 U2.22(COMP)
DAD_OEZ: J1.14A R1.1 R4.2
DADADDR_0: J1.13E U5.6(A4)
DADADDR_1: J1.13C U5.7(A5)
DADADDR_2: J1.12E U5.8(A6)
DADADDR_3: J1.12D U5.9(A7)
DADIRQZ: J1.11C R37.2
DADMODE_0: J1.11F U5.4(A2)
DADMODE_1: J1.11E U5.5(A3)
DADOEZ: C5.1 R4.1 U6.5(A3)
DADSEL_0: J1.12B U6.3(A1)
DADSEL_1: J1.12A U6.4(A2)
DADSTRB: J1.13F U5.3(A1)
DCLK_AN: J2.21E U3.B6(DCLK_AN)
DCLK_AP: J2.21F U3.B5(DCLK_AP)
DCLK_BN: J2.5E U3.Z6(DCLK_BN)
DCLK_BP: J2.5F U3.Z5(DCLK_BP)
DCLK_CN: J1.5E U3.G26(DCLK_CN)
DCLK_CP: J1.5F U3.F26(DCLK_CP)
DCLK_DN: J1.21E U3.U26(DCLK_DN)
DCLK_DP: J1.21F U3.V26(DCLK_DP)
DD_AN0: J2.16A U3.C7(D_AN_0)
DD_AN1: J2.17E U3.D4(D_AN_1)
DD_AN2: J2.17B U3.C5(D_AN_2)
DD_AN3: J2.18D U3.D6(D_AN_3)
DD_AN4: J2.18A U3.D8(D_AN_4)
DD_AN5: J2.19E U3.D3(D_AN_5)
DD_AN6: J2.19B U3.B3(D_AN_6)
DD_AN7: J2.20D U3.E11(D_AN_7)
DD_AN8: J2.21B U3.E6(D_AN_8)
DD_AN9: J2.22D U3.B10(D_AN_9)
DD_AN10: J2.22A U3.B8(D_AN_10)
DD_AN11: J2.23E U3.C13(D_AN_11)
DD_AN12: J2.23B U3.D15(D_AN_12)
DD_AN13: J2.24D U3.B12(D_AN_13)
DD_AN14: J2.24A U3.B15(D_AN_14)
DD_AN15: J2.25B U3.C16(D_AN_15)
DD_AP0: J2.16B U3.C8(D_AP_0)
DD_AP1: J2.17F U3.E4(D_AP_1)
DD_AP2: J2.17C U3.C4(D_AP_2)
DD_AP3: J2.18E U3.C6(D_AP_3)
DD_AP4: J2.18B U3.D7(D_AP_4)
DD_AP5: J2.19F U3.E3(D_AP_5)
DD_AP6: J2.19C U3.C3(D_AP_6)
DD_AP7: J2.20E U3.E10(D_AP_7)
DD_AP8: J2.21C U3.E5(D_AP_8)
DD_AP9: J2.22E U3.C10(D_AP_9)
DD_AP10: J2.22B U3.B9(D_AP_10)
DD_AP11: J2.23F U3.C14(D_AP_11)
DD_AP12: J2.23C U3.E15(D_AP_12)
DD_AP13: J2.24E U3.B13(D_AP_13)
DD_AP14: J2.24B U3.B16(D_AP_14)
DD_AP15: J2.25C U3.C17(D_AP_15)
DD_BN0: J2.10A U3.Y8(D_BN_0)
DD_BN1: J2.9E U3.X4(D_BN_1)
DD_BN2: J2.9B U3.Z3(D_BN_2)
DD_BN3: J2.8D U3.X6(D_BN_3)
DD_BN4: J2.8A U3.X8(D_BN_4)
DD_BN5: J2.7E U3.X3(D_BN_5)
DD_BN6: J2.7B U3.W15(D_BN_6)
DD_BN7: J2.6D U3.W11(D_BN_7)
DD_BN8: J2.5B U3.W6(D_BN_8)
DD_BN9: J2.4D U3.AA9(D_BN_9)
DD_BN10: J2.4A U3.Z8(D_BN_10)
DD_BN11: J2.3E U3.Y13(D_BN_11)
DD_BN12: J2.3B U3.Z10(D_BN_12)
DD_BN13: J2.2D U3.Z12(D_BN_13)
DD_BN14: J2.2A U3.Z15(D_BN_14)
DD_BN15: J2.1E U3.Y16(D_BN_15)
DD_BP0: J2.10B U3.Y7(D_BP_0)
DD_BP1: J2.9F U3.W4(D_BP_1)
DD_BP2: J2.9C U3.Y3(D_BP_2)
DD_BP3: J2.8E U3.Y6(D_BP_3)
DD_BP4: J2.8B U3.X7(D_BP_4)
DD_BP5: J2.7F U3.W3(D_BP_5)
DD_BP6: J2.7C U3.X15(D_BP_6)
DD_BP7: J2.6E U3.W10(D_BP_7)
DD_BP8: J2.5C U3.W5(D_BP_8)
DD_BP9: J2.4E U3.AA10(D_BP_9)
DD_BP10: J2.4B U3.Z9(D_BP_10)
DD_BP11: J2.3F U3.Y14(D_BP_11)
DD_BP12: J2.3C U3.Y10(D_BP_12)
DD_BP13: J2.2E U3.Z13(D_BP_13)
DD_BP14: J2.2B U3.Z16(D_BP_14)
DD_BP15: J2.1F U3.Y17(D_BP_15)
DD_CN0: J1.10A U3.C18(D_CN_0)
DD_CN1: J1.9E U3.A20(D_CN_1)
DD_CN2: J1.9B U3.L23(D_CN_2)
DD_CN3: J1.8D U3.C23(D_CN_3)
DD_CN4: J1.8A U3.G23(D_CN_4)
DD_CN5: J1.7E U3.H24(D_CN_5)
DD_CN6: J1.7B U3.B18(D_CN_6)
DD_CN7: J1.6D U3.C21(D_CN_7)
DD_CN8: J1.5B U3.D23(D_CN_8)
DD_CN9: J1.4D U3.D25(D_CN_9)
DD_CN10: J1.4A U3.L24(D_CN_10)
DD_CN11: J1.3E U3.K25(D_CN_11)
DD_CN12: J1.3B U3.B24(D_CN_12)
DD_CN13: J1.2D U3.D26(D_CN_13)
DD_CN14: J1.2A U3.G25(D_CN_14)
DD_CN15: J1.1E U3.K26(D_CN_15)
DD_CP0: J1.10B U3.C19(D_CP_0)
DD_CP1: J1.9F U3.A19(D_CP_1)
DD_CP2: J1.9C U3.K23(D_CP_2)
DD_CP3: J1.8E U3.B23(D_CP_3)
DD_CP4: J1.8B U3.H23(D_CP_4)
DD_CP5: J1.7F U3.G24(D_CP_5)
DD_CP6: J1.7C U3.B19(D_CP_6)
DD_CP7: J1.6E U3.B21(D_CP_7)
DD_CP8: J1.5C U3.E23(D_CP_8)
DD_CP9: J1.4E U3.C25(D_CP_9)
DD_CP10: J1.4B U3.K24(D_CP_10)
DD_CP11: J1.3F U3.J25(D_CP_11)
DD_CP12: J1.3C U3.A24(D_CP_12)
DD_CP13: J1.2E U3.C26(D_CP_13)
DD_CP14: J1.2B U3.F25(D_CP_14)
DD_CP15: J1.1F U3.J26(D_CP_15)
DD_DN0: J1.25B U3.Y18(D_DN_0)
DD_DN1: J1.24A U3.AA20(D_DN_1)
DD_DN2: J1.24D U3.N23(D_DN_2)
DD_DN3: J1.23B U3.Y23(D_DN_3)
DD_DN4: J1.23E U3.U23(D_DN_4)
DD_DN5: J1.22A U3.T24(D_DN_5)
DD_DN6: J1.22D U3.Z18(D_DN_6)
DD_DN7: J1.21B U3.Y21(D_DN_7)
DD_DN8: J1.20D U3.X23(D_DN_8)
DD_DN9: J1.19B U3.X25(D_DN_9)
DD_DN10: J1.19E U3.N24(D_DN_10)
DD_DN11: J1.18A U3.P25(D_DN_11)
DD_DN12: J1.18D U3.Z24(D_DN_12)
DD_DN13: J1.17B U3.X26(D_DN_13)
DD_DN14: J1.17E U3.U25(D_DN_14)
DD_DN15: J1.16A U3.P26(D_DN_15)
DD_DP0: J1.25C U3.Y19(D_DP_0)
DD_DP1: J1.24B U3.AA19(D_DP_1)
DD_DP2: J1.24E U3.P23(D_DP_2)
DD_DP3: J1.23C U3.Z23(D_DP_3)
DD_DP4: J1.23F U3.T23(D_DP_4)
DD_DP5: J1.22B U3.U24(D_DP_5)
DD_DP6: J1.22E U3.Z19(D_DP_6)
DD_DP7: J1.21C U3.Z21(D_DP_7)
DD_DP8: J1.20E U3.W23(D_DP_8)
DD_DP9: J1.19C U3.Y25(D_DP_9)
DD_DP10: J1.19F U3.P24(D_DP_10)
DD_DP11: J1.18B U3.R25(D_DP_11)
DD_DP12: J1.18E U3.AA24(D_DP_12)
DD_DP13: J1.17C U3.Y26(D_DP_13)
DD_DP14: J1.17F U3.V25(D_DP_14)
DD_DP15: J1.16B U3.R26(D_DP_15)
DMD_EN_OFFSET: U3.H3(EN_OFFSET) U7.6(2A1)
DMD_P1P8V: C10.2 C31.1 C32.1 C35.1 C36.1 C37.1 C41.1 C42.1 C43.1 C44.1 C45.1 C46.1 C51.2 C52.1 C53.1 C54.1 C55.1 C56.1 C57.1 C58.1 C59.1 C60.1 C61.1 C62.1 C63.1 C64.1 C65.1 C66.1 C67.1 C68.1 C69.1 C70.1 C71.1 C72.1 C73.1 C74.1 C75.1 C76.1 C77.1 C78.1 C79.1 C80.1 C81.1 C82.1 C83.1 C84.1 C85.1 C86.1 C87.1 C88.1 C89.1 C90.1 R27.1 R41.1 R42.1 TP32.1 U1.4(VOUT) U3.A8(VCC) U3.A11(VCCI) U3.A16(VCCI) U3.A17(VCCI) U3.A18(VCCI) U3.A21(VCCI) U3.A22(VCCI) U3.A23(VCCI) U3.AA2(VCC) U3.AA8(VCC) U3.AA11(VCCI) U3.AA16(VCCI) U3.AA17(VCCI) U3.AA18(VCCI) U3.AA21(VCCI) U3.AA22(VCCI) U3.AA23(VCCI) U3.B2(VCC) U3.C1(VCC) U3.D1(VCC) U3.D10(VCC) U3.D12(VCC) U3.D19(VCC) U3.E1(VCC) U3.E19(VCC) U3.E20(VCC) U3.E21(VCC) U3.F1(VCC) U3.K1(VCC) U3.L1(VCC) U3.M1(VCC) U3.N1(VCC) U3.P1(VCC) U3.V1(VCC) U3.W1(VCC) U3.W19(VCC) U3.W20(VCC) U3.W21(VCC) U3.X1(VCC) U3.X10(VCC) U3.X12(VCC) U3.X19(VCC) U3.Y1(VCC) U3.Z1(VCC) U3.Z2(VCC) U5.23(VCCB) U5.24(VCCB) U6.23(VCCB) U6.24(VCCB) U7.1(VCCA) U7.2(1DIR) U7.3(2DIR)
DMD_P3P3V: C1.1 C2.1 C7.1 C9.1 C11.2 C12.2 C29.1 C33.1 C34.1 C38.1 J3.1 J4.3 L1.2 L2.2 L3.1 L4.1 L5.1 R1.2 R2.2 R3.2 R8.1 R30.2 R31.2 TP1.1 U1.1(EN) U1.2(VIN) U2.4(Vin) U4.1(VCC) U5.1(VCCA) U5.2(DIR) U6.1(VCCA) U6.2(DIR) U7.16(VCCB)
DMD_RSTZ: J1.15B R2.1 U6.9(A7)
DMD_SCP_CLK: R53.2 U3.W17(SCPCLK)
DMD_SCP_DI: R42.2 U3.W16(SCPDO) U7.4(1A1)
DMD_SCP_DO: R54.2 U3.W18(SCPDI)
DRV: C19.2 U2.18(DRV)
DRV_1: C19.1 D4.3(K1)
DRV_D: C13.1 D5.3(K1)
EN_BIAS: R39.1 U3.J4(EN_BIAS)
EN_OFFSET: J3.2 Q2.1(G) R16.2 R20.1 TP4.1 U2.24(EN) U7.11(2B1)
EN_RESET: R40.1 U3.J3(EN_RESET)
Ext_Voffset: J5.3 R731.1
FB1: C14.2 R18.2 R19.1 U2.1(FB1)
FB2: R22.2 R23.1 U2.21(FB2)
FB3: R25.2 R26.2 U2.12(FB3)
IRQZ: R41.2 U3.U3(IRQZ) U7.7(2A2)
MBRST0: TP10.1 U3.E13(MBRST_0)
MBRST1: TP11.1 U3.C12(MBRST_1)
MBRST2: TP12.1 U3.D13(MBRST_2)
MBRST3: TP13.1 U3.C11(MBRST_3)
MBRST4: TP14.1 U3.E14(MBRST_4)
MBRST5: TP15.1 U3.E12(MBRST_5)
MBRST6: TP16.1 U3.C15(MBRST_6)
MBRST7: TP17.1 U3.D16(MBRST_7)
MBRST8: TP18.1 U3.W13(MBRST_8)
MBRST9: TP19.1 U3.Y12(MBRST_9)
MBRST10: TP20.1 U3.X13(MBRST_10)
MBRST11: TP21.1 U3.Y11(MBRST_11)
MBRST12: TP22.1 U3.W14(MBRST_12)
MBRST13: TP23.1 U3.W12(MBRST_13)
MBRST14: TP25.1 U3.Y15(MBRST_14)
MBRST15: TP24.1 U3.X16(MBRST_15)
MODE_0: R44.2 U3.P4(MODE0)
MODE_1: R45.2 U3.V3(MODE1)
OEZ: R52.2 U3.R2(OEZ)
P3P3V1: C3.1 J1.1B J1.1C L1.1
P3P3V2: C4.1 J2.1B J2.1C L2.1
P3P3V3: C6.1 J1.25E J1.25F L3.2
P3P3V4: C8.1 J2.25E J2.25F L4.2
PG: C28.1 R28.1 U2.10(PG)
PG_BIAS: R39.2 U3.K3(PG_BIAS)
PG_OFFSET: R27.2 R28.2 TP7.1 U3.F2(PG_OFFSET)
PG_RESET: R40.2 U3.F3(PG_RESET)
PLM_TP: C104.1 J5.1 TP44.1 U3.G2(TP_2)
REF: C25.1 R22.1 U2.20(REF)
RSTZ: R56.2 U3.G3(PWRDNZ) U3.U4(RESETZ)
SCL: J4.1 R31.1 U4.8(SCL)
SCP_CLK: J1.16D U6.6(A4)
SCP_CSZ: R55.2 U3.X18(SCPENZ) U7.15(1OEZ)
SCP_DI: J1.15C R36.2
SCP_DMD_CSZ: J1.15E R3.1 U6.8(A6)
SCP_DO: J1.16E U6.7(A5)
SCTRL_AN: J2.20A U3.A10(SCTRL_AN)
SCTRL_AP: J2.20B U3.A9(SCTRL_AP)
SCTRL_BN: J2.6A U3.Y4(SCTRL_BN)
SCTRL_BP: J2.6B U3.Y5(SCTRL_BP)
SCTRL_CN: J1.6A U3.E24(SCTRL_CN)
SCTRL_CP: J1.6B U3.D24(SCTRL_CP)
SCTRL_DN: J1.20A U3.W24(SCTRL_DN)
SCTRL_DP: J1.20B U3.X24(SCTRL_DP)
SDA: J4.2 R30.1 U4.7(SDA)
SEL_0: R50.2 U3.P3(SEL0)
SEL_1: R51.2 U3.V2(SEL1)
STRB: R43.2 U3.W8(STROBE)
SW0_1: C13.2 D3.1(ANODE) L5.2 U2.5(SW0) U2.6(SW1)
VBIAS: C26.2 C27.1 C98.1 C99.1 C100.1 C101.1 C102.1 C103.1 R6.1 R21.2 R25.1 TP6.1 U2.13(OUT3) U3.A5(VBIAS) U3.A6(VBIAS) U3.A7(VBIAS) U3.AA5(VBIAS) U3.AA6(VBIAS) U3.AA7(VBIAS)
VOFF: C14.1 C15.1 C16.1 D3.2(CATHODE) R18.1 R730.1 U2.9(SUP_OUT1)
VOFFSET: C91.1 C92.1 C93.1 C94.1 C95.1 C96.1 C97.1 D2.1(CATHODE) Q9.1(D) Q9.2(D) Q9.5(D) Q9.6(D) Q9.DPad(D_pad) R5.1 R13.2 TP3.1 U3.A3(VOFFSET) U3.A4(VOFFSET) U3.A25(VOFFSET) U3.AA3(VOFFSET) U3.AA4(VOFFSET) U3.AA25(VOFFSET) U3.B26(VOFFSET) U3.L26(VOFFSET) U3.M26(VOFFSET) U3.N26(VOFFSET) U3.Z26(VOFFSET)
VRESET: C22.1 C23.2 C24.1 C39.1 C40.1 C47.1 C48.1 C49.1 C50.1 D5.1(A1) Q1.2(S) R7.1 R23.2 TP5.1 U3.G1(VRESET) U3.H1(VRESET) U3.J1(VRESET) U3.R1(VRESET) U3.T1(VRESET) U3.U1(VRESET)
N25259737: C17.2 R17.1
N25259806: C20.1 D4.1(A1) D5.2(K2)
N25259992: C21.1 Q8.3(DRAIN)
N25632003: Q8.2(GATE) R21.1 R24.1
N25668037: R43.1 U5.21(B1)
N25668039: R44.1 U5.20(B2)
N25668056: R45.1 U5.19(B3)
N25668068: R46.1 U5.18(B4)
N25668080: R47.1 U5.17(B5)
N25668082: R48.1 U5.16(B6)
N25668084: R49.1 U5.15(B7)
N25668435: R50.1 U6.21(B1)
N25668437: R51.1 U6.20(B2)
N25668439: R52.1 U6.19(B3)
N25668441: R53.1 U6.18(B4)
N25668443: R54.1 U6.17(B5)
N25668445: R55.1 U6.16(B6)
N25668447: R56.1 U6.15(B7)
N25679971: R36.1 U7.13(1B1)
N25707269: Q9.3(G) R14.1 R15.1
N25707285: Q9.4(S) Q9.SPad(S_pad) R13.1 R14.2 R730.2 R731.2
N25707305: Q7.3(COLLECTOR) R15.2
N25707317: Q7.2(BASE) R20.2
N25709651: Q2.3(D) Q3.1(G) Q4.1(G) Q5.2(S) R8.2
N25709778: D1.2(ANODE) Q4.3(D)
N25709784: R5.2 R9.1
N25709786: R6.2 R10.1
N25709788: Q3.3(D) R10.2
N25709790: Q1.1(G) Q5.3(D) R7.2
N25709817: R11.2 R12.1
N25709819: Q1.3(D) R11.1
N25711925: TP29.1 U3.N4(BIST_A)
N25711930: TP28.1 U3.K4(BIST_B)
N25711935: TP27.1 U3.X17(BIST_C)
N25711940: TP26.1 U3.D17(BIST_D)
N25715846: C30.1 R32.2 U3.E16(TEMP_P)
N25715868: R32.1 U4.2(D+)
N25715873: C30.2 R33.2 U3.E17(TEMP_N)
N25715880: R33.1 U4.3(D-)
N25721950: R34.2 U5.10(A8)
N25722220: R35.2 U6.10(A8)
N25722470: R38.2 U7.5(1A2)
N25784260: R37.1 U7.10(2B2)
N25903568: D1.1(CATHODE) R9.2

Not connected (* = marked no-connect by the designer): J1 10D 10E* 11B* 13A* 13B* 14B* 14D* 14E* 15F*; J2 10D 10E 11B 11C* 11E* 11F* 12A* 12B* 12D* 12E* 13A* 13B* 13C* 13E* 13F* 14A* 14B* 14D* 14E* 15B* 15C* 15E* 15F* 16D* 16E*; U1 5(ERROR); U2 2(FB4)* 3(BASE)*; U3 E8(TP_0)* E18(PROG_FUSE_EN)* G4(TEST_MUX)* J2(TP_1)*; U4 4(THERM) 6(ALERT); U5 14(B8); U6 14(B8); U7 12(1B2)

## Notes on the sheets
sheet 1
- DLPLCR67EVM-DLP041
sheet 2
- COMPUTER GENERATED DRAWING - DO NOT REVISE MANUALLY
- NOTES, UNLESS OTHERWISE SPECIFIED:
- REVISIONS
- REV
- DESCRIPTION
- DATE
- APPROVED
- 1. The netname "DMD_P3P3V" represents connection to the +3.3V digital power plane.
- A
- Initial Release
- 7/15/2020
- B
- L5 reduction
- 3/17/2025
- 2. The symbol
- represents connection to the digital ground plane.
- 3. A "Z" suffix on a signal name indicates an active low signal.
- 4. All components with designators "U", "D", "Y" and "Q" are electrostatic discharge sensitive.
- 5. All resistor values are in ohms, 1/16W and 5% unless otherwise specified.
- HIGHEST REFERENCE DESIGNATORS USED
- U7
- C103
- D5
- J4
- L5
- R56
- TP31
- Q9
sheet 3
- U3
  DLP670S
- J1 & J2
  Input Flex
  Connector
- A/B DMD DATA (DD_AP[15:0], DD_AN[15:0], DD_BP[15:0], DD_BN[15:0])
- From
  Slave
  ASIC
- A/B DMD CLK (DCLK_AP, DCLK_AN, DCLK_BP, DCLK_BN)
- A/B SCTRL (SCTRL_AN, SCTRL_AP, SCTRL_BN, SCTRL_BP)
- C/D DMD DATA (DD_CP[15:0], DD_CN[15:0], DD_DP[15:0], DD_DN[15:0])
- C/D DMD CLK (DCLK_CP, DCLK_CN, DCLK_DP, DCLK_DN)
- From
  Master
  ASIC
- C/D SCTRL (SCTRL_CN, SCTRL_CP, SCTRL_DN, SCTRL_DP)
- U5, U6, U7
  Level Translators
  3.3V->1.8V
- DAD CONTROL (STROBE, MODE[1:0], SEL[1:0], ADDR[3:0], OEZ)
- SCP CONTROL  (CLK, DO, DI, ENZ, IRQZ)
- DMD_RSTZ
- U1
  VREG
  3.3V->1.8V
- U2
  DMD Power Supplies
- 3.3V
- VOFFSET
- VBIAS
- VRESET
- PG_OFFSET
- EN_OFFSET
- PAGE 3
- PAGE 4
- PAGE 5 & 6
- DLPLCR67EVM-DLP041
sheet 4
- Slave LVDS
- Master LVDS
- Note: Do not install R3 if
  there is a pull-up on the
  SCP_DMD_CSZ signal on the
  Main board.
- Note: Only install one 1K Ohm
  pull-up resistor on DAD_OEZ. If
  DAD_OEZ pull-up is installed on
  Main board side, do not install
  R1.
- 12V is not used on
  pins 10D, 10E, 11B
- Note: R4 and C5 are specific
  values selected to delay ASIC
  driven DAD_OEZ to allow the DMD
  enough time to park properly.
  Recommend installing values as
  shown.
- Board Instances
- INPUT CONNECTOR
- DLPLCR67EVM-DLP041
sheet 5
- Power Down Circuitry
- 10.0V
- 11V protection diode
- -14.0V
- 18.0V
- DMD Power Supplies
- DLPLCR67EVM-DLP041
sheet 6
- DMD Power/Gnd
- DLPLCR67EVM-DLP041
sheet 7
- Bring TP for reset waveform
  MBRST 0,15 outside of DMD
  outline
- Do Not Install
- DMD Data/Control
- DLPLCR67EVM-DLP041
